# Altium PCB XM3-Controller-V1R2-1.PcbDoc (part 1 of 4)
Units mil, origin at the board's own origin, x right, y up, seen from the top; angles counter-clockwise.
Board outline 10629.92 x 4173.11 mil, 6 copper layers (TOP, GND1, LAYER3, PWR, GND2, BOTTOM), stack 62 mil thick; 362 components, 276 nets, 1145 pads, 503 vias.
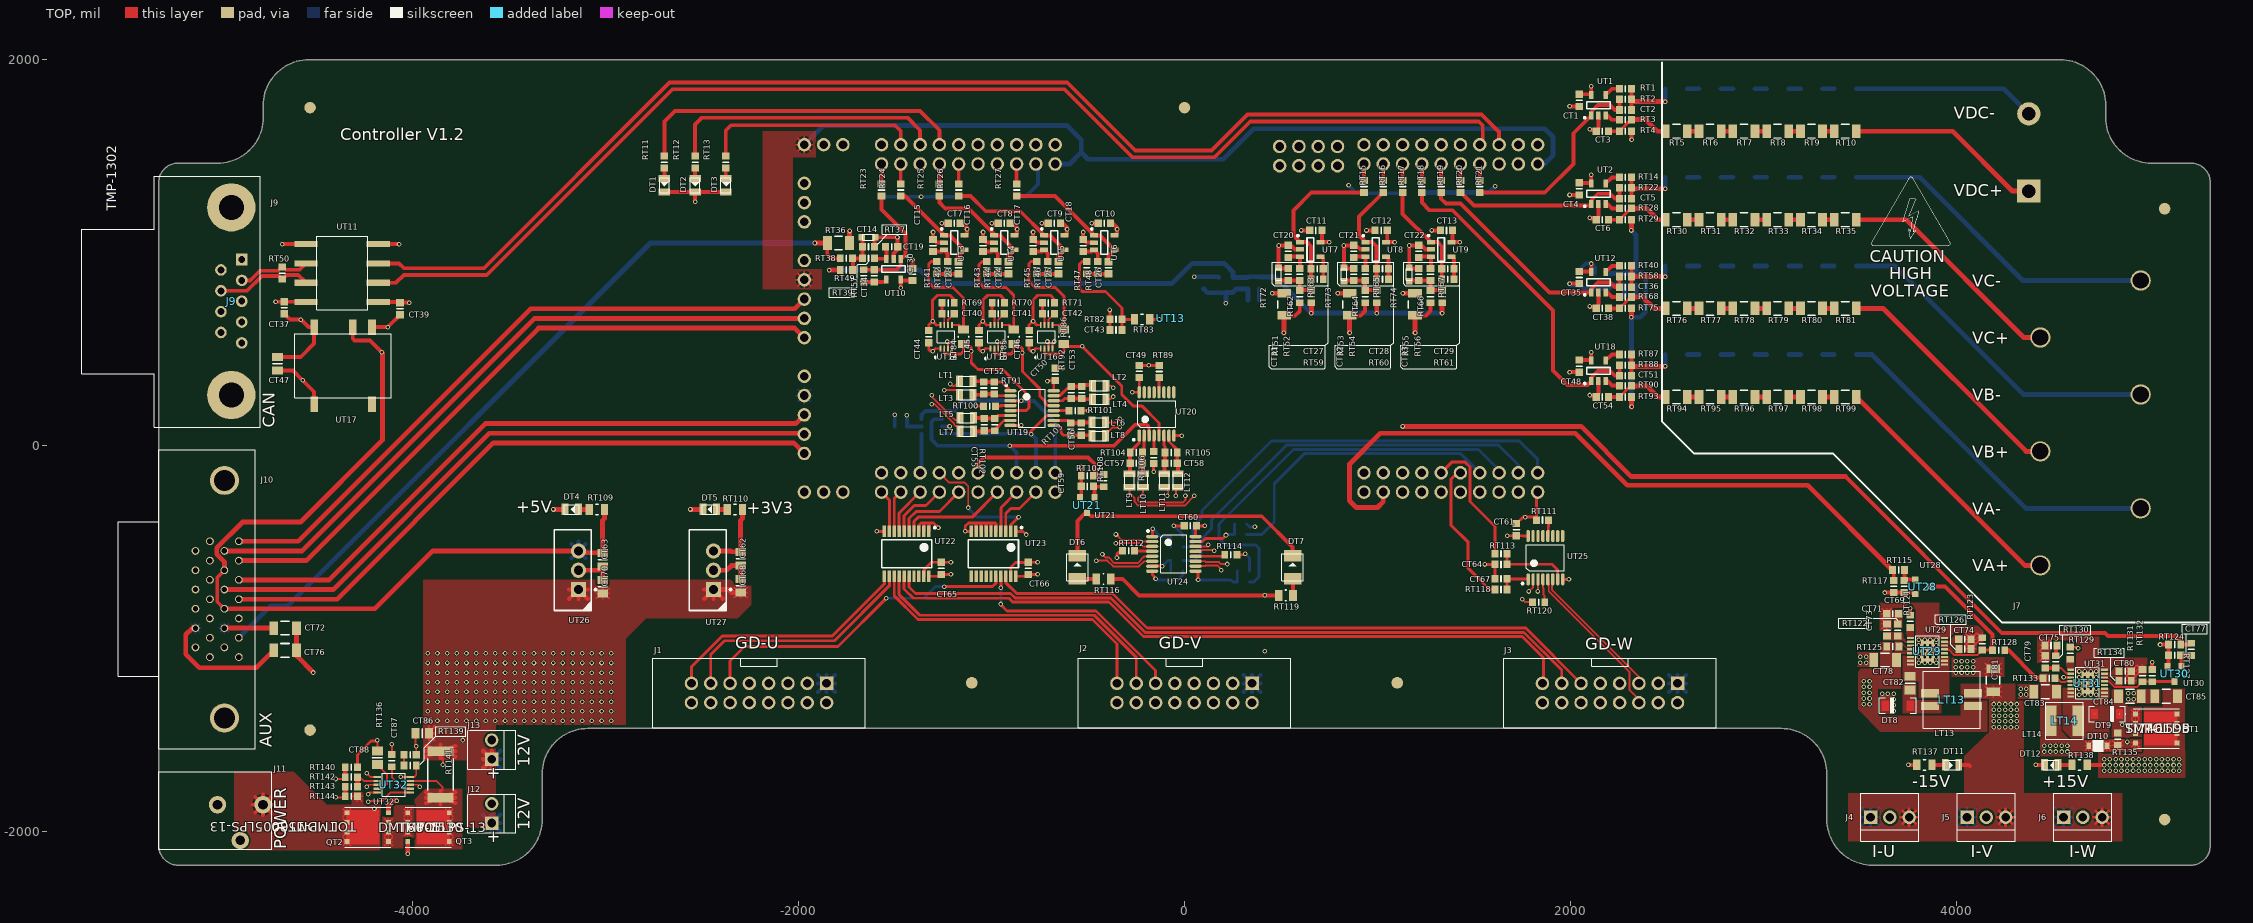
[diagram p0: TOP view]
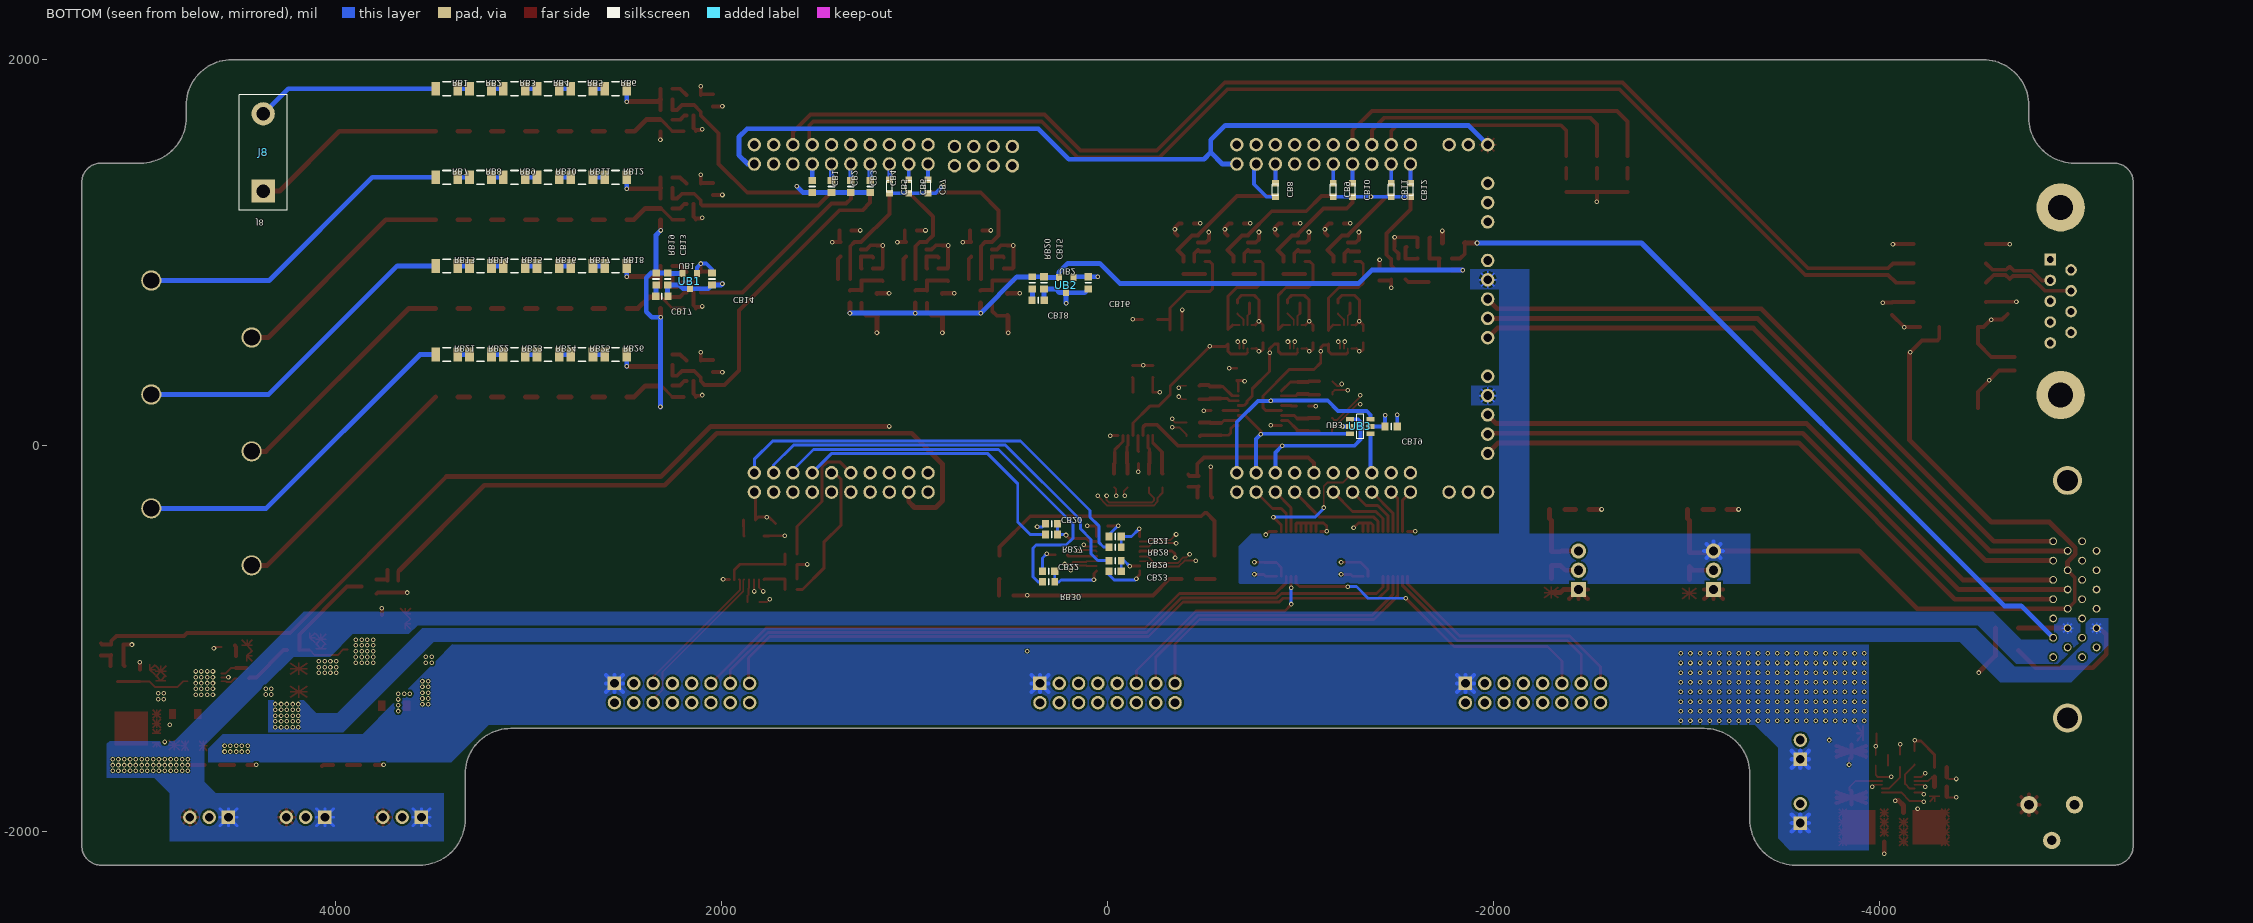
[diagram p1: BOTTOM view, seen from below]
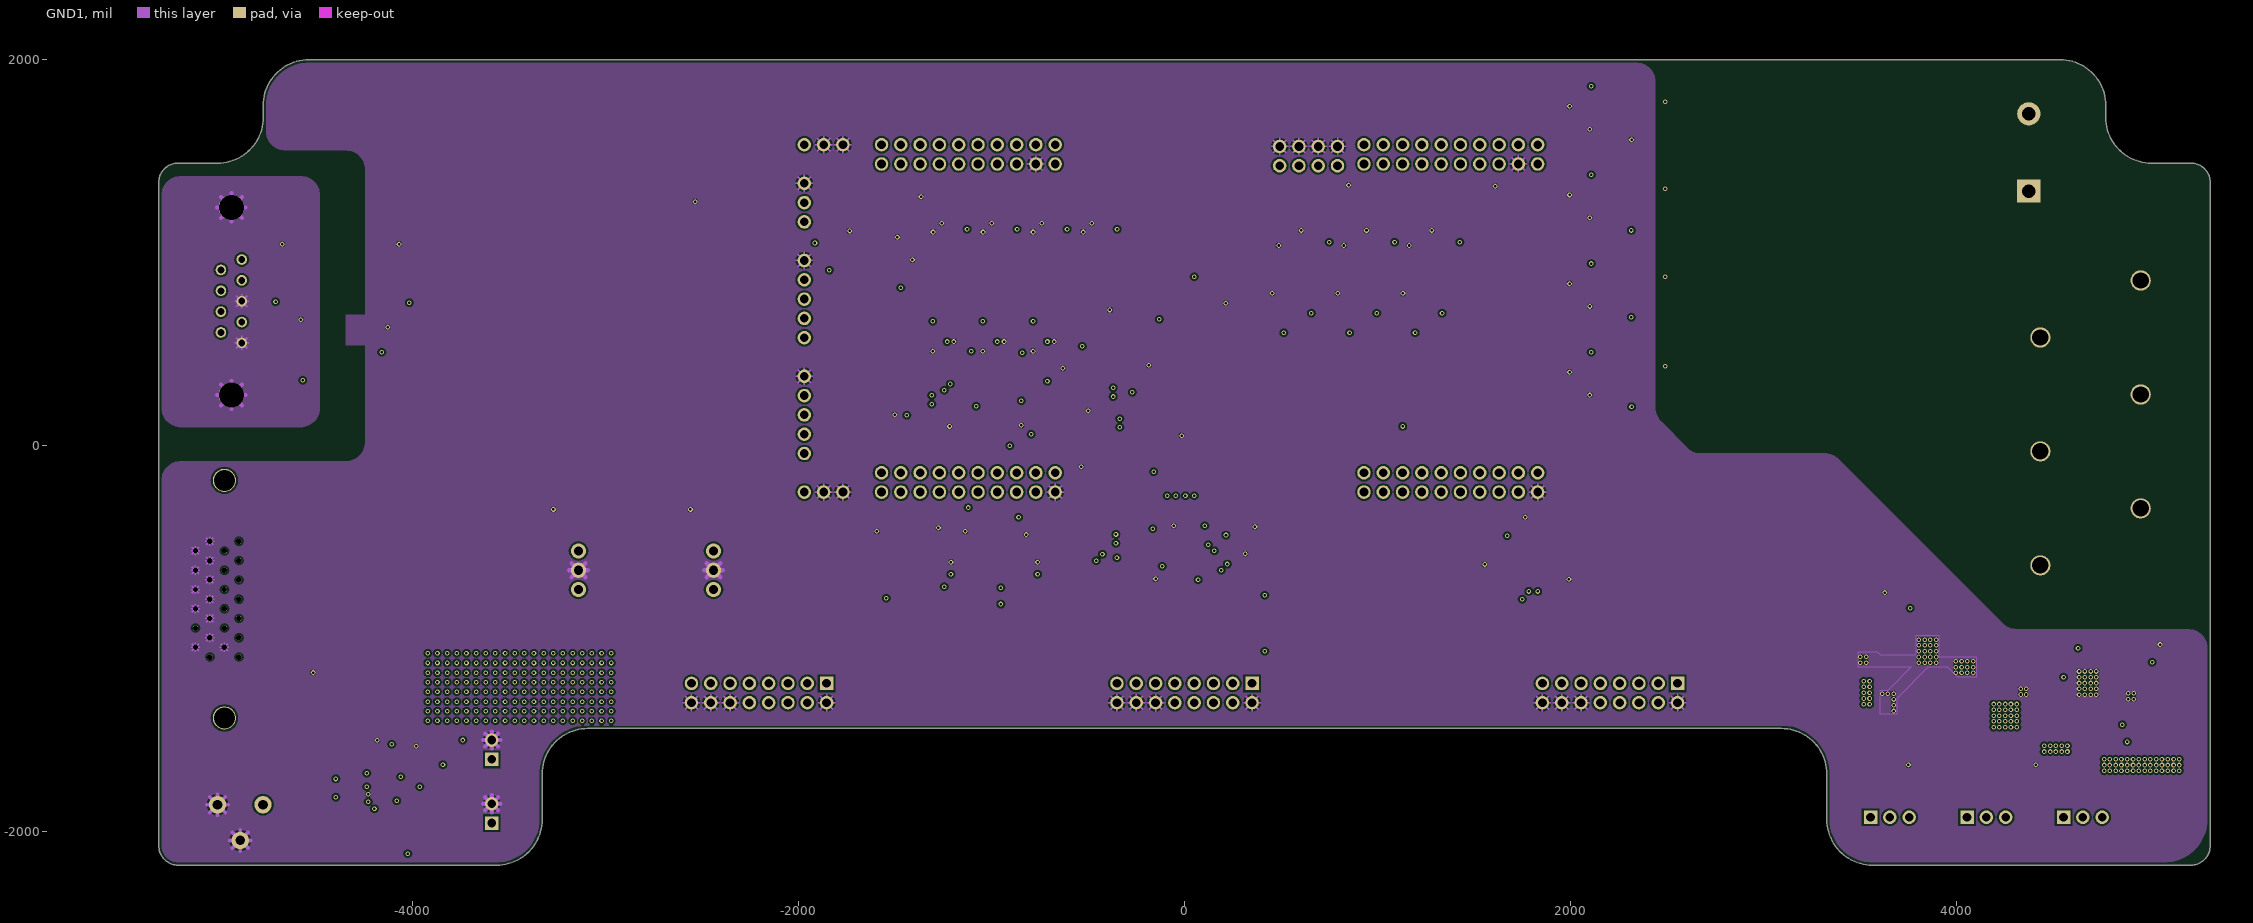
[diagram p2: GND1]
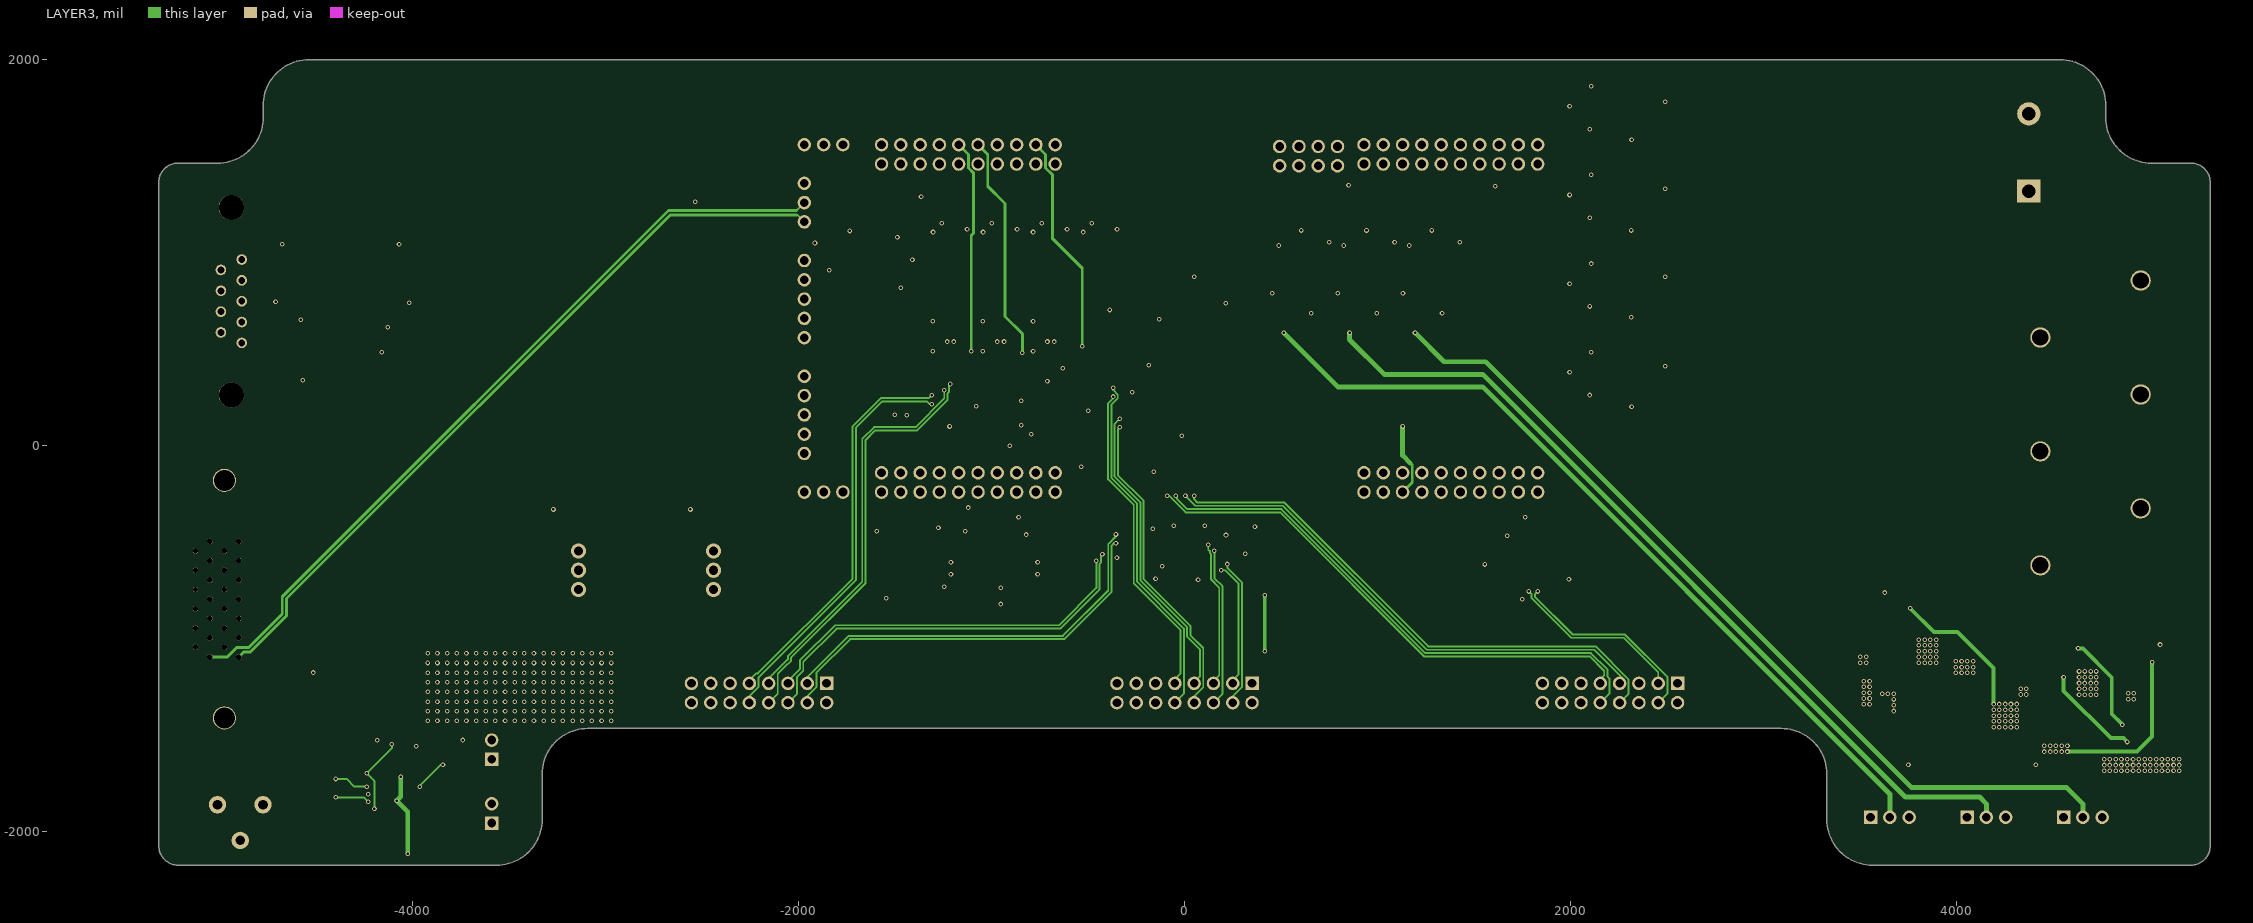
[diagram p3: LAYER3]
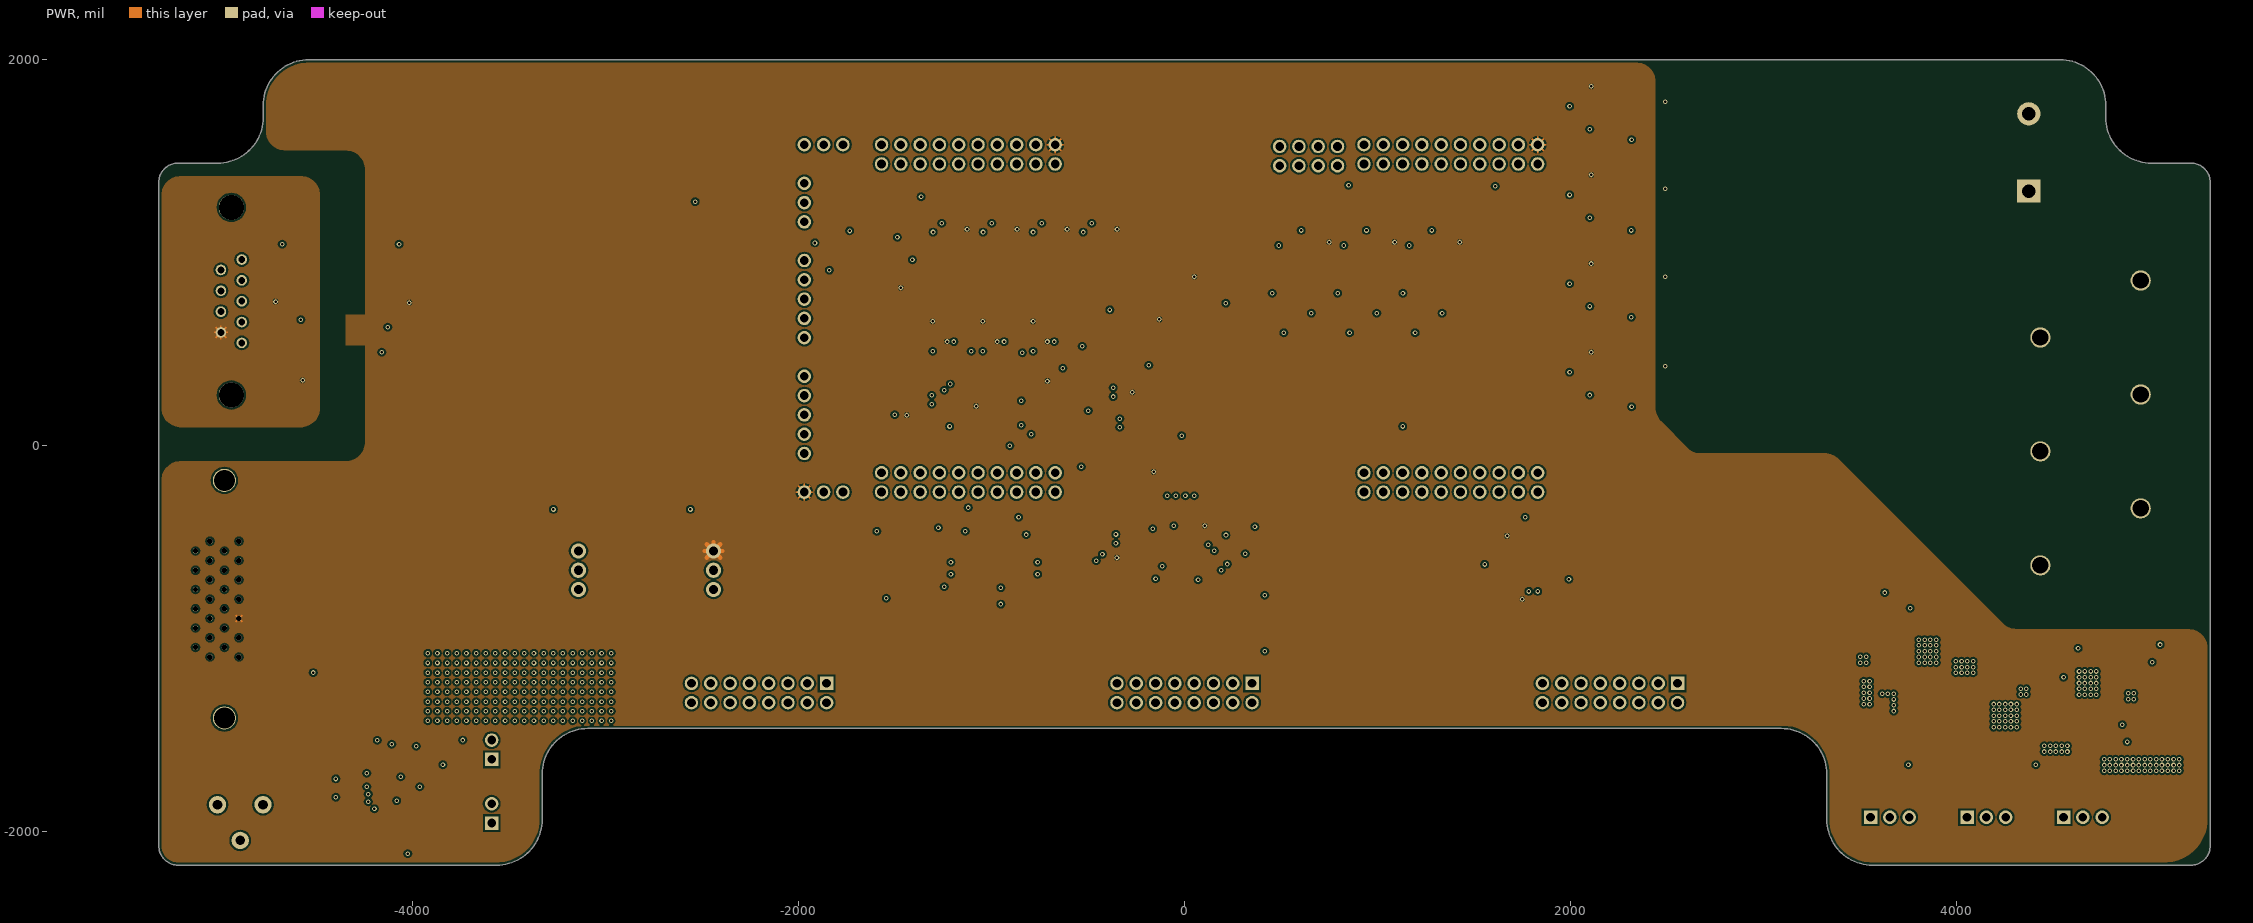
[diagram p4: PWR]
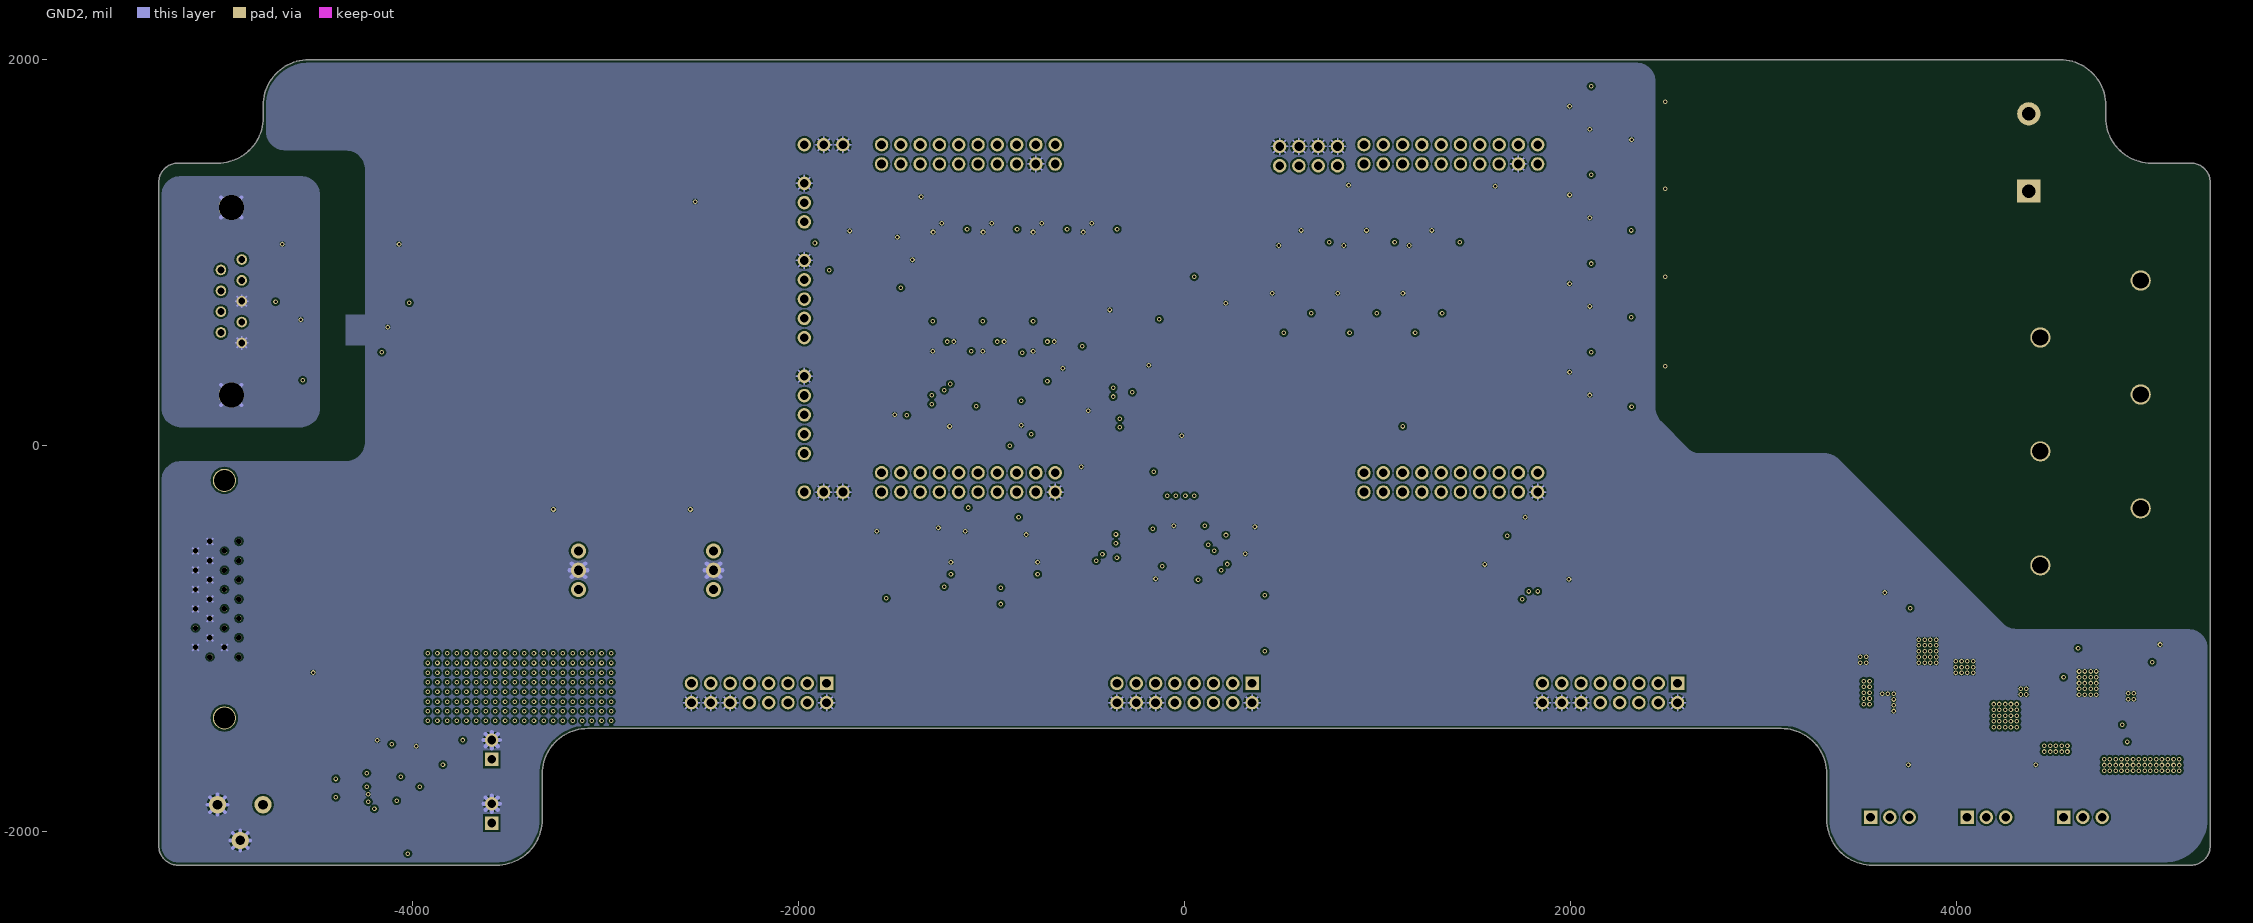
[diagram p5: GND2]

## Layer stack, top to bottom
Top Solder: solder mask 0.4, Solder Resist, Dk 3.5
TOP: signal copper 1.4
Dielectric 1: core 8, FR-4, Dk 4.5
GND1: signal copper 1.4
Dielectric2: core 8, FR-4, Dk 4.5
LAYER3: signal copper 1.4
Dielectric3: core 21.6, FR-4, Dk 4.5
PWR: signal copper 1.4
Dielectric4: core 8, FR-4, Dk 4.5
GND2: signal copper 1.4
Dielectric5: core 8, FR-4, Dk 4.5
BOTTOM: signal copper 1.4
Bottom Solder: solder mask 0.4, Solder Resist, Dk 3.5

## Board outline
-5009.84,1464.57 ccw(c-5009.84,1700.79) -4773.62,1700.79 -4773.62,1763.78 cw(c-4537.4,1763.78) -4537.4,2000 4537.4,2000 cw(c4537.4,1763.78) 4773.62,1763.78 4773.62,1700.79 ccw(c5009.84,1700.79) 5009.84,1464.57 5214.96,1464.57 cw(c5214.96,1364.57) 5314.96,1364.57 5314.96,-2073.11 cw(c5214.96,-2073.11) 5214.96,-2173.11 3564.68,-2173.11 cw(c3564.68,-1936.89) 3328.46,-1936.89 3328.46,-1700.79 ccw(c3092.24,-1700.79) 3092.24,-1464.57 -3092.24,-1464.57 ccw(c-3092.24,-1700.79) -3328.46,-1700.79 -3328.46,-1936.89 cw(c-3564.68,-1936.89) -3564.68,-2173.11 -5214.96,-2173.11 cw(c-5214.96,-2073.11) -5314.96,-2073.11 -5314.96,1364.57 cw(c-5214.96,1364.57) -5214.96,1464.57

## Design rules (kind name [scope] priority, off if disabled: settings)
Clearance [All] p1: gap=10 ignorepadtopadclearanceinfootprint=FALSE
DiffPairsRouting [All] p1: maxlimit=10 minlimit=10 mostfreqgap=10 toplayer_minwidth=15 toplayer_maxwidth=15 toplayer_prefwidth=15 midlayer1_minwidth=15 midlayer1_maxwidth=15 midlayer1_prefwidth=15 midlayer2_minwidth=15 midlayer2_maxwidth=15 midlayer2_prefwidth=15 midlayer3_minwidth=15 midlayer3_maxwidth=15 midlayer3_prefwidth=15 midlayer4_minwidth=15 midlayer4_maxwidth=15 midlayer4_prefwidth=15 bottomlayer_minwidth=15 bottomlayer_maxwidth=15 bottomlayer_prefwidth=15 maxuncoupledlength=500
PlaneConnect [All] p1: planeconnectstyle=Direct reliefexpansion=20 reliefentries=4 reliefconductorwidth=10 reliefairgap=10
PolygonConnect [All] p1: connectstyle=Direct reliefconductorwidth=10 reliefentries=4 polygonreliefangle="90 Angle" airgapwidth=10
RoutingVias [All] p1: holewidth=28 width=50 viastyle="Through Hole" minholewidth=28 minwidth=50 maxholewidth=28 maxwidth=50
SolderMaskExpansion [All] p1: expansion=4 istentingtop=FALSE
Width [All] p1: maxlimit=10 minlimit=10 preferedwidth=10 impedanceprofiledriven=TRUE minimp=24.700000 maximp=192.210000 favimp=19.760000
28 further rules are at their usual default settings.

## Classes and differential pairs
net class VBM: N45813 N45817 N45821 N51246 N51250 VB-M
differential pair C-RTD-: +C-RTD-N -C-RTD-P
differential pair CLS-PWM-: +CLS-PWM-N -CLS-PWM-P
differential pair CHS-PWM-: +CHS-PWM-N -CHS-PWM-P
differential pair C-FAULT-: +C-FAULT-N -C-FAULT-P
differential pair CANB: +CANBH -CANBL
differential pair CANA: +CANA-H -CANA-L
differential pair B-RTD-: +B-RTD-N -B-RTD-P
differential pair BLS-PWM-: +BLS-PWM-N -BLS-PWM-P
differential pair BHS-PWM-: +BHS-PWM-N -BHS-PWM-P
differential pair B-FAULT-: +B-FAULT-N -B-FAULT-P
differential pair A-RTD-: +A-RTD-N -A-RTD-P
differential pair ALS-PWM-: +ALS-PWM-N -ALS-PWM-P
differential pair AHS-PWM-: +AHS-PWM-N -AHS-PWM-P
differential pair A-FAULT-: +A-FAULT-N -A-FAULT-P

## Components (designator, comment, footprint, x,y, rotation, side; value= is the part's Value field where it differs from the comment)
CB1 "CAP_CAPC1608X90N_DISCRETE_0.27" CAPC1608X90N#1 1530,1343.5 r90 bottom
CB2 "CAP_CAPC1608X90N_DISCRETE_0.27" CAPC1608X90N#1 1430,1343.5 r90 bottom
CB3 "CAP_CAPC1608X90N_DISCRETE_0.27" CAPC1608X90N#1 1330,1343.5 r90 bottom
CB4 "CAP_CAPC1608X90N_DISCRETE_0.27" CAPC1608X90N#1 1230,1343.5 r90 bottom
CB5 "CAP_C_0603_DISCRETE_4700PF_TMP-" C_0603#1 1130,1343.5 r90 bottom
CB6 "CAP_C_0603_DISCRETE_4700PF_TMP-" C_0603#1 1030,1343.5 r90 bottom
CB7 "CAP_C_0603_DISCRETE_4700PF_TMP-" C_0603#1 930,1343.5 r90 bottom
CB8 "CAP_C_0603_DISCRETE_4700PF_TMP-" C_0603#1 -870,1325.22 r90 bottom
CB9 "CAP_C_0603_DISCRETE_4700PF_TMP-" C_0603#1 -1170,1325.22 r90 bottom
CB10 "CAP_C_0603_DISCRETE_4700PF_TMP-" C_0603#1 -1270,1325.22 r90 bottom
CB11 "CAP_C_0603_DISCRETE_4700PF_TMP-" C_0603#1 -1470,1325.22 r90 bottom
CB12 "CAP_C_0603_DISCRETE_4700PF_TMP-" C_0603#1 -1570,1325.22 r90 bottom
CB13 "CAP_CAPC1608X90N_DISCRETE_10000" CAPC1608X90N#1 2279.25,864.17 r90 bottom
CB14 "CAP_CAPC1608X87N_DISCRETE_0.1UF" CAPC1608X87N#1 2049.25,864.17 r90 bottom
CB15 "CAP_CAPC1608X90N_DISCRETE_10000" CAPC1608X90N#1 329.25,844.16 r90 bottom
CB16 "CAP_CAPC1608X87N_DISCRETE_0.1UF" CAPC1608X87N#1 99.25,844.16 r90 bottom
CB17 "CAP_CAPC1608X90N_DISCRETE_10UF_" CAPC1608X90N#2 2309.25,774.17 r180 bottom
CB18 "CAP_CAPC1608X90N_DISCRETE_10UF_" CAPC1608X90N#2 359.25,754.16 r180 bottom
CB19 "CAP_CAPC1608X87N_DISCRETE_0.1UF" CAPC1608X87N#2 -1470,100 r180 bottom
CB20 "CAP_CAPC1608X90N_DISCRETE_100PF" CAPC1608X90N#2 290,-405 r0 bottom
CB21 "CAP_CAPC1608X90N_DISCRETE_100PF" CAPC1608X90N#2 -40,-470 r0 bottom
CB22 "CAP_CAPC1608X90N_DISCRETE_100PF" CAPC1608X90N#2 305,-650 r0 bottom
CB23 "CAP_CAPC1608X90N_DISCRETE_100PF" CAPC1608X90N#2 -40,-650 r0 bottom
CT1 "CAP_CAPC1608X87N_DISCRETE_0.1UF" CAPC1608X87N#2 2045,1790 r270 top
CT2 "CAP_CAPC1608X90N_DISCRETE_4700P" CAPC1608X90N#2 2285,1740 r180 top
CT3 "CAP_CAPC1608X90N_DISCRETE_4700P" CAPC1608X90N#2 2165,1630 r0 top
CT4 "CAP_CAPC1608X87N_DISCRETE_0.1UF" CAPC1608X87N#2 2045,1330.94 r270 top
CT5 "CAP_CAPC1608X90N_DISCRETE_10000" CAPC1608X90N#2 2285,1280.94 r180 top
CT6 "CAP_CAPC1608X90N_DISCRETE_10000" CAPC1608X90N#2 2165,1170.94 r0 top
CT7 "CAP_CAPC1608X87N_DISCRETE_0.1UF" CAPC1608X87N#2 -1193.15,1152.4 r180 top
CT8 "CAP_CAPC1608X87N_DISCRETE_0.1UF" CAPC1608X87N#2 -933.97,1152.4 r180 top
CT9 "CAP_CAPC1608X87N_DISCRETE_0.1UF" CAPC1608X87N#2 -674.79,1152.4 r180 top
CT10 "CAP_CAPC1608X87N_DISCRETE_0.1UF" CAPC1608X87N#2 -415.61,1152.4 r180 top
CT11 "CAP_CAPC1608X87N_DISCRETE_0.1UF" CAPC1608X87N#2 680.44,1115.66 r180 top
CT12 "CAP_CAPC1608X87N_DISCRETE_0.1UF" CAPC1608X87N#2 1018.96,1115.66 r180 top
CT13 "CAP_CAPC1608X87N_DISCRETE_0.1UF" CAPC1608X87N#2 1357.48,1115.66 r180 top
CT14 "CAP_C_0603_DISCRETE_4700PF_TMP-" C_0603#2 -1637.5,1080.64 r0 top
CT15 "CAP_CAPC1608X90N_DISCRETE_10000" CAPC1608X90N#2 -1303.15,1037.4 r270 top
CT16 "CAP_CAPC1608X90N_DISCRETE_10000" CAPC1608X90N#2 -1043.97,1037.4 r270 top
CT17 "CAP_CAPC1608X90N_DISCRETE_10000" CAPC1608X90N#2 -784.79,1037.4 r270 top
CT18 "CAP_CAPC1608X90N_DISCRETE_4700P" CAPC1608X90N#2 -525.61,1037.4 r270 top
CT19 "CAP_CAPC1608X90N_DISCRETE_100PF" CAPC1608X90N#2 -1517.5,1030.64 r0 top
CT20 "CAP_CAPC1608X90N_DISCRETE_100PF" CAPC1608X90N#2 537.5,1007.69 r90 top
CT21 "CAP_CAPC1608X90N_DISCRETE_100PF" CAPC1608X90N#2 876.02,1007.69 r90 top
CT22 "CAP_CAPC1608X90N_DISCRETE_100PF" CAPC1608X90N#2 1214.54,1007.69 r90 top
CT23 "CAP_CAPC1608X90N_DISCRETE_10000" CAPC1608X90N#2 -1171.27,922.4 r90 top
CT24 "CAP_CAPC1608X90N_DISCRETE_10000" CAPC1608X90N#2 -912.09,922.4 r90 top
CT25 "CAP_CAPC1608X90N_DISCRETE_10000" CAPC1608X90N#2 -652.91,922.4 r90 top
CT26 "CAP_CAPC1608X90N_DISCRETE_10000" CAPC1608X90N#2 -393.73,922.4 r90 top
CT27 "CAP_CAPC1608X90N_DISCRETE_100PF" CAPC1608X90N#2 687.5,917.69 r180 top
CT28 "CAP_CAPC1608X90N_DISCRETE_100PF" CAPC1608X90N#2 1026.02,917.69 r180 top
CT29 "CAP_CAPC1608X90N_DISCRETE_100PF" CAPC1608X90N#2 1364.54,917.69 r180 top
CT30 "CAP_CAPC1608X87N_DISCRETE_0.1UF" CAPC1608X87N#2 -1409.53,887.7 r90 top
CT31 "CAP_C_0603_DISCRETE_4700PF_TMP-" C_0603#2 487.5,887.69 r90 top
CT32 "CAP_C_0603_DISCRETE_4700PF_TMP-" C_0603#2 826.02,887.69 r90 top
CT33 "CAP_C_0603_DISCRETE_4700PF_TMP-" C_0603#2 1164.54,887.69 r90 top
CT34 "CAP_CAPC1608X90N_DISCRETE_100PF" CAPC1608X90N#2 -1607.5,880.64 r90 top
CT35 "CAP_CAPC1608X87N_DISCRETE_0.1UF" CAPC1608X87N#2 2045,871.88 r270 top
CT36 "CAP_CAPC1608X90N_DISCRETE_10000" CAPC1608X90N#2 2285,821.88 r180 top
CT37 "CAP_CAPC1608X87N_DISCRETE_0.1UF" CAPC1608X87N#2 -4665,715 r270 top
CT38 "CAP_CAPC1608X90N_DISCRETE_10000" CAPC1608X90N#2 2165,711.88 r0 top
CT39 "CAP_CAPC1608X87N_DISCRETE_0.1UF" CAPC1608X87N#2 -4065,710 r270 top
CT40 "CAP_CAPC1608X90N_DISCRETE_10000" CAPC1608X90N#2 -1225,685 r0 top
CT41 "CAP_CAPC1608X90N_DISCRETE_10000" CAPC1608X90N#2 -965,685 r0 top
CT42 "CAP_CAPC1608X90N_DISCRETE_10000" CAPC1608X90N#2 -705,685 r0 top
CT43 "CAP_CAPC1608X90N_DISCRETE_100PF" CAPC1608X90N#2 -355,600 r0 top
CT44 "CAP_CAPC1608X87N_DISCRETE_0.1UF" CAPC1608X87N#2 -1325,565 r270 top
CT45 "CAP_CAPC1608X87N_DISCRETE_0.1UF" CAPC1608X87N#2 -1065,565 r270 top
CT46 "CAP_CAPC1608X87N_DISCRETE_0.1UF" CAPC1608X87N#2 -805,565 r270 top
CT47 "CAP_CAPC2012X135N_DISCRETE_10UF" CAPC2012X135N -4700,425 r90 top
CT48 "CAP_CAPC1608X87N_DISCRETE_0.1UF" CAPC1608X87N#2 2045,412.82 r270 top
CT49 "CAP_CAPC1608X87N_DISCRETE_0.1UF" CAPC1608X87N#2 -235,385 r90 top
CT50 "CAP_CAPC1608X87N_DISCRETE_0.1UF" CAPC1608X87N#2 -670,370 r90 top
CT51 "CAP_CAPC1608X90N_DISCRETE_10000" CAPC1608X90N#2 2285,362.82 r180 top
CT52 "CAP_CAPC1608X90N_DISCRETE_27PF_" CAPC1608X90N#2 -1040.5,299.17 r90 top
CT53 "CAP_CAPC1608X90N_DISCRETE_27PF_" CAPC1608X90N#2 -531.5,275.84 r90 top
CT54 "CAP_CAPC1608X90N_DISCRETE_10000" CAPC1608X90N#2 2165,252.82 r0 top
CT55 "CAP_CAPC1608X90N_DISCRETE_27PF_" CAPC1608X90N#2 -1038.5,109.17 r270 top
CT56 "CAP_CAPC1608X90N_DISCRETE_27PF_" CAPC1608X90N#2 -534.5,85.84 r270 top
CT57 "CAP_CAPC1608X90N_DISCRETE_27PF_" CAPC1608X90N#2 -250,-90 r180 top
CT58 "CAP_CAPC1608X90N_DISCRETE_27PF_" CAPC1608X90N#2 -69.16,-90 r0 top
CT59 "CAP_CAPC1608X90N_DISCRETE_100PF" CAPC1608X90N#2 -503.29,-210.85 r180 top
CT60 "CAP_CAPC1608X87N_DISCRETE_0.1UF" CAPC1608X87N#2 30,-415 r180 top
CT61 "CAP_CAPC1608X87N_DISCRETE_0.1UF" CAPC1608X87N#2 1720,-435 r90 top
CT62 "CAP_CAPC2012X135N_DISCRETE_10UF" CAPC2012X135N -2300,-585 r270 top
CT63 "CAP_CAPC2012X135N_DISCRETE_10UF" CAPC2012X135N -3015,-590 r270 top
CT64 "CAP_CAPC1608X90N_DISCRETE_100PF" CAPC1608X90N#2 1640,-615 r180 top
CT65 "CAP_CAPC1608X87N_DISCRETE_0.1UF" CAPC1608X87N#2 -1260,-635 r90 top
CT66 "CAP_CAPC1608X87N_DISCRETE_0.1UF" CAPC1608X87N#2 -810,-635 r90 top
CT67 "CAP_CAPC1608X90N_DISCRETE_100PF" CAPC1608X90N#2 1640,-690 r180 top
CT68 "CAP_CAPC2012X135N_DISCRETE_10UF" CAPC2012X135N -2300,-725 r90 top
CT69 "CAP_CAPC1608X90N_DISCRETE_100PF" CAPC1608X90N#2 3730,-729 r270 top
CT70 "CAP_CAPC2012X135N_DISCRETE_10UF" CAPC2012X135N -3015,-730 r90 top
CT71 "CAP_CAPC1608X90N_DISCRETE_1000P" CAPC1608X90N#2 3670,-870 r180 top
CT72 "CAP_CAPC3216X180N_DISCRETE_10 U" CAPC3216X180N -4660,-945 r0 top
CT73 "CAP_CAPC1608X90N_DISCRETE_56 PF" CAPC1608X90N#2 3640,-955 r270 top
CT74 "CAP_CAPC1608X90N_DISCRETE_0.1UF" CAPC1608X90N#2 4044,-1003 r180 top
CT75 "CAP_CAPC1608X90N_DISCRETE_1000P" CAPC1608X90N#2 4490,-1035 r180 top
CT76 "CAP_CAPC3216X180N_DISCRETE_10 U" CAPC3216X180N -4660,-1060 r0 top
CT77 "CAP_CAPC1608X90N_DISCRETE_100PF" CAPC1608X90N#2 5131,-1085.01 r180 top
CT78 "CAP_CAPC3216X180N_DISCRETE_4.7U" CAPC3216X180N 3630,-1110 r180 top
CT79 "CAP_CAPC1608X90N_DISCRETE_56 PF" CAPC1608X90N#2 4460,-1120 r270 top
CT80 "CAP_CAPC1608X90N_DISCRETE_0.1UF" CAPC1608X90N#2 4874,-1168 r180 top
CT81 "CAP_CAPC3216X180N_DISCRETE_10 U" CAPC3216X180N 4190,-1215 r90 top
CT82 "CAP_CAPC2012X70N_DISCRETE_1UF_T" CAPC2012X70N 3760,-1230 r270 top
CT83 "CAP_CAPC3216X180N_DISCRETE_4.7U" CAPC3216X180N 4460,-1275 r180 top
CT84 "CAP_CAPC3216X180N_DISCRETE_4.7U" CAPC3216X180N 4899,-1298 r0 top
CT85 "CAP_CAPC3216X180N_DISCRETE_10 U" CAPC3216X180N 5087,-1298 r180 top
CT86 "CAP_CAPC2012X135N_DISCRETE_10UF" CAPC2012X135N -3950,-1490 r180 top
CT87 "CAP_CAPC1608X90N_DISCRETE_4700P" CAPC1608X90N#2 -4012.5,-1601.67 r0 top
CT88 "CAP_CAPC2012X70N_DISCRETE_0.022" CAPC2012X70N -4182.5,-1616.67 r90 top
DT1 "LED_0_D_0805_DISCRETE_LH R974-L" D_0805 -2695,1350 r270 top
DT2 "LED_0_D_0805_DISCRETE_LTST-C1_1" D_0805 -2535.94,1350 r270 top
DT3 "LED_0_D_0805_DISCRETE_LG R971-K" D_0805 -2376.88,1350 r270 top
DT4 "LED_0_D_0805_DISCRETE_LTST-C171" D_0805 -3175,-330 r180 top
DT5 "LED_0_D_0805_DISCRETE_LTST-C171" D_0805 -2460,-330 r180 top
DT6 "LED - PURPLE_D_1409_DISCRETE_AA" D_1409 -555,-630 r90 top
DT7 "LED - PURPLE_D_1409_DISCRETE_AA" D_1409 560,-630 r90 top
DT8 "DIODE_SCHOTTKY_0_SOD-123F-AC_DI" SOD-123F-AC 3696,-1347 r180 top
DT9 "DIODE_SCHOTTKY_0_SOD-123F-AC_DI" SOD-123F-AC 4780,-1390 r0 top
DT10 "DIODE_SCHOTTKY_C2_A1_0_SOD-323-" SOD-323-AC 4730,-1555 r0 top
DT11 "LED_0_D_0805_DISCRETE_LTST-C171" D_0805 3977,-1653.47 r0 top
DT12 "LED_0_D_0805_DISCRETE_LTST-C171" D_0805 4491,-1653.47 r180 top
J1 "CON16A_CORRECTED_CON_2X8_SHROUD" CON_2X8_SHROUDED_CORRECTED -2204.72,-1281.36 r270 top
J2 "CON16A_CORRECTED_CON_2X8_SHROUD" CON_2X8_SHROUDED_CORRECTED 0,-1281.36 r270 top
J3 "CON16A_CORRECTED_CON_2X8_SHROUD" CON_2X8_SHROUDED_CORRECTED 2204.72,-1281.36 r270 top
J4 "CON3_CON_1X3_VERT_LOCK_IO_00222" CON_1X3_VERT_LOCK 3655,-1925 r90 top
J5 "CON3_CON_1X3_VERT_LOCK_IO_00222" CON_1X3_VERT_LOCK 4155,-1925 r90 top
J6 "CON3_CON_1X3_VERT_LOCK_IO_00222" CON_1X3_VERT_LOCK 4655,-1925 r90 top
J7 "HDR_1X6_M_PHOENIX_SPT5_6PIN_IO_" PHOENIX_SPT5_6PIN 4835.59,41.42 r90 top
J8 "CON2_2POS_400MIL_TERMINAL_CON2" 2POS_400MIL_TERMINAL 4375,1520 r270 bottom
J9 "DSUB - NI CAN INTERFACE_0_DB9_I" DB9 -5263,749 r90 top
J10 "CONN CENT RCPT 26_MDR-26_IO_102" MDR-26 -5170,-795 r270 top
J11 "POWER_JACK_POWERJACK-PJ102AH_IO" POWERJACK-PJ102AH -5022.5,-1890 r270 top
J12 "1X2 100MIL_CON_1X2_VERT_LOCK_IO" CON_1X2_VERT_LOCK -3590,-1905 r180 top
J13 "1X2 100MIL_CON_1X2_VERT_LOCK_IO" CON_1X2_VERT_LOCK -3590,-1575 r180 top
LT1 "INDUCTOR_L_0805_DISCRETE_1UH_TM" L_0805 -1130.5,334.17 r0 top
LT2 "INDUCTOR_L_0805_DISCRETE_1UH_TM" L_0805 -441.5,310.84 r180 top
LT3 "INDUCTOR_L_0805_DISCRETE_1UH_TM" L_0805 -1130.5,264.17 r0 top
LT4 "INDUCTOR_L_0805_DISCRETE_1UH_TM" L_0805 -441.5,240.84 r180 top
LT5 "INDUCTOR_L_0805_DISCRETE_1UH_TM" L_0805 -1128.5,144.17 r0 top
LT6 "INDUCTOR_L_0805_DISCRETE_1UH_TM" L_0805 -444.5,120.84 r180 top
LT7 "INDUCTOR_L_0805_DISCRETE_1UH_TM" L_0805 -1128.5,74.17 r0 top
LT8 "INDUCTOR_L_0805_DISCRETE_1UH_TM" L_0805 -444.5,50.84 r180 top
LT9 "INDUCTOR_L_0805_DISCRETE_1UH_TM" L_0805 -285,-180 r90 top
LT10 "INDUCTOR_L_0805_DISCRETE_1UH_TM" L_0805 -215,-180 r90 top
LT11 "INDUCTOR_L_0805_DISCRETE_1UH_TM" L_0805 -104.16,-180 r90 top
LT12 "INDUCTOR_L_0805_DISCRETE_1UH_TM" L_0805 -34.16,-180 r90 top
LT13 "COUPLED_INDUCTOR_IND-MSD7342_6." IND-MSD7342 3975,-1315 r180 top
LT14 "IND_IND-5040_DISCRETE_3.3UH_TMP" IND-5040 4560,-1425 r0 top
QT1 "MOSFET_P_PSO8_POWER-SO8_DISCRET" POWER-SO8 5035,-1465 r0 top
QT2 "MOSFET_N_PSO8_POWER-SO8_DISCRET" POWER-SO8 -4232.5,-1976.67 r180 top
QT3 "MOSFET_N_PSO8_POWER-SO8_DISCRET" POWER-SO8 -3917.5,-1976.67 r0 top
RB1 "RES_RESC3216X65N_DISCRETE_249 K" RESC3216X65N 3423.59,1850 r180 bottom
RB2 "RES_RESC3216X65N_DISCRETE_249 K" RESC3216X65N 3248.59,1850 r180 bottom
RB3 "RES_RESC3216X65N_DISCRETE_249 K" RESC3216X65N 3073.59,1850 r180 bottom
RB4 "RES_RESC3216X65N_DISCRETE_249 K" RESC3216X65N 2898.59,1850 r180 bottom
RB5 "RES_RESC3216X65N_DISCRETE_249 K" RESC3216X65N 2723.59,1850 r180 bottom
RB6 "RES_RESC3216X65N_DISCRETE_249 K" RESC3216X65N 2548.59,1850 r180 bottom
RB7 "RES_RESC3216X65N_DISCRETE_249 K" RESC3216X65N 3423.59,1390.94 r180 bottom
RB8 "RES_RESC3216X65N_DISCRETE_249 K" RESC3216X65N 3248.59,1390.94 r180 bottom
RB9 "RES_RESC3216X65N_DISCRETE_249 K" RESC3216X65N 3073.58,1390.94 r180 bottom
RB10 "RES_RESC3216X65N_DISCRETE_249 K" RESC3216X65N 2898.59,1390.94 r180 bottom
RB11 "RES_RESC3216X65N_DISCRETE_249 K" RESC3216X65N 2723.59,1390.94 r180 bottom
RB12 "RES_RESC3216X65N_DISCRETE_249 K" RESC3216X65N 2548.59,1390.94 r180 bottom
RB13 "RES_RESC3216X65N_DISCRETE_249 K" RESC3216X65N 3423.59,931.88 r180 bottom
RB14 "RES_RESC3216X65N_DISCRETE_249 K" RESC3216X65N 3248.59,931.88 r180 bottom
RB15 "RES_RESC3216X65N_DISCRETE_249 K" RESC3216X65N 3073.58,931.88 r180 bottom
RB16 "RES_RESC3216X65N_DISCRETE_249 K" RESC3216X65N 2898.59,931.88 r180 bottom
RB17 "RES_RESC3216X65N_DISCRETE_249 K" RESC3216X65N 2723.59,931.88 r180 bottom
RB18 "RES_RESC3216X65N_DISCRETE_249 K" RESC3216X65N 2548.59,931.88 r180 bottom
RB19 "RES_RESC1608X55N_DISCRETE_2K_TM" RESC1608X55N#1 2339.25,864.17 r90 bottom
RB20 "RES_RESC1608X55N_DISCRETE_2K_TM" RESC1608X55N#1 389.25,844.16 r90 bottom
RB21 "RES_RESC3216X65N_DISCRETE_249 K" RESC3216X65N 3423.59,472.82 r180 bottom
RB22 "RES_RESC3216X65N_DISCRETE_249 K" RESC3216X65N 3248.59,472.82 r180 bottom
RB23 "RES_RESC3216X65N_DISCRETE_249 K" RESC3216X65N 3073.58,472.82 r180 bottom
RB24 "RES_RESC3216X65N_DISCRETE_249 K" RESC3216X65N 2898.59,472.82 r180 bottom
RB25 "RES_RESC3216X65N_DISCRETE_249 K" RESC3216X65N 2723.59,472.82 r180 bottom
RB26 "RES_RESC3216X65N_DISCRETE_249 K" RESC3216X65N 2548.59,472.82 r180 bottom
RB27 "R_RESC1608X55N_DISCRETE_120_TMP" RESC1608X55N#2 290,-460 r180 bottom
RB28 "R_RESC1608X55N_DISCRETE_120_TMP" RESC1608X55N#2 -40,-525 r180 bottom
RB29 "R_RESC1608X55N_DISCRETE_120_TMP" RESC1608X55N#2 -40,-595 r180 bottom
RB30 "R_RESC1608X55N_DISCRETE_120_TMP" RESC1608X55N#2 305,-705 r180 bottom
RT1 "RES_RESC1608X55N_DISCRETE_4.99K" RESC1608X55N#2 2285,1850 r180 top
RT2 "RES_RESC1608X55N_DISCRETE_3.74" RESC1608X55N#2 2285,1795 r180 top
RT3 "RES_RESC1608X55N_DISCRETE_4.99K" RESC1608X55N#2 2285,1688.94 r180 top
RT4 "RES_RESC1608X55N_DISCRETE_3.74" RESC1608X55N#2 2285,1630 r180 top
RT5 "RES_RESC3216X65N_DISCRETE_249 K" RESC3216X65N 2548.59,1630 r180 top
RT6 "RES_RESC3216X65N_DISCRETE_249 K" RESC3216X65N 2723.59,1630 r180 top
RT7 "RES_RESC3216X65N_DISCRETE_249 K" RESC3216X65N 2898.59,1630 r180 top
RT8 "RES_RESC3216X65N_DISCRETE_249 K" RESC3216X65N 3073.59,1630 r180 top
RT9 "RES_RESC3216X65N_DISCRETE_249 K" RESC3216X65N 3248.59,1630 r180 top
RT10 "RES_RESC3216X65N_DISCRETE_249 K" RESC3216X65N 3423.59,1630 r180 top
RT11 "RES_RESC1608X55N_DISCRETE_680_T" RESC1608X55N#2 -2695,1470 r270 top
RT12 "RES_RESC1608X55N_DISCRETE_680_T" RESC1608X55N#2 -2535.94,1470 r270 top
RT13 "RES_RESC1608X55N_DISCRETE_680_T" RESC1608X55N#2 -2376.88,1470 r270 top
RT14 "RES_RESC1608X55N_DISCRETE_4.99K" RESC1608X55N#2 2285,1390.94 r180 top
RT15 "RES_RESC1608X55N_DISCRETE_49.9_" RESC1608X55N#2 930,1343.5 r90 top
RT16 "RES_RESC1608X55N_DISCRETE_49.9_" RESC1608X55N#2 1030,1343.5 r90 top
RT17 "RES_RESC1608X55N_DISCRETE_49.9_" RESC1608X55N#2 1130,1343.5 r90 top
RT18 "RES_RESC1608X55N_DISCRETE_49.9_" RESC1608X55N#2 1230,1343.5 r90 top
RT19 "RES_RESC1608X55N_DISCRETE_49.9_" RESC1608X55N#2 1330,1343.5 r90 top
RT20 "RES_RESC1608X55N_DISCRETE_49.9_" RESC1608X55N#2 1430,1343.5 r90 top
RT21 "RES_RESC1608X55N_DISCRETE_49.9_" RESC1608X55N#2 1530,1343.5 r90 top
RT22 "RES_RESC1608X55N_DISCRETE_1.8 K" RESC1608X55N#2 2285,1335.94 r180 top
RT23 "RES_RESC1608X55N_DISCRETE_49.9_" RESC1608X55N#2 -1570,1325.22 r90 top
RT24 "RES_RESC1608X55N_DISCRETE_49.9_" RESC1608X55N#2 -1470,1325.22 r90 top
RT25 "RES_RESC1608X55N_DISCRETE_49.9_" RESC1608X55N#2 -1270,1325.22 r90 top
RT26 "RES_RESC1608X55N_DISCRETE_49.9_" RESC1608X55N#2 -1170,1325.22 r90 top
RT27 "RES_RESC1608X55N_DISCRETE_49.9_" RESC1608X55N#2 -870,1325.22 r90 top
RT28 "RES_RESC1608X55N_DISCRETE_4.99K" RESC1608X55N#2 2285,1229.88 r180 top
RT29 "RES_RESC1608X55N_DISCRETE_1.8 K" RESC1608X55N#2 2285,1170.94 r180 top
RT30 "RES_RESC3216X65N_DISCRETE_249 K" RESC3216X65N 2548.6,1170.94 r180 top
RT31 "RES_RESC3216X65N_DISCRETE_249 K" RESC3216X65N 2723.6,1170.95 r180 top
RT32 "RES_RESC3216X65N_DISCRETE_249 K" RESC3216X65N 2898.58,1170.94 r180 top
RT33 "RES_RESC3216X65N_DISCRETE_249 K" RESC3216X65N 3073.6,1170.94 r180 top
RT34 "RES_RESC3216X65N_DISCRETE_249 K" RESC3216X65N 3248.6,1170.94 r180 top
RT35 "RES_RESC3216X65N_DISCRETE_249 K" RESC3216X65N 3423.58,1170.94 r180 top
RT36 "RES_RESC3216X65N_DISCRETE_27_TM" RESC3216X65N -1792.5,1050.64 r0 top
RT37 "R_RESC1608X55N_DISCRETE_4.02 KO" RESC1608X55N#2 -1637.5,1030.64 r180 top
RT38 "RES_RESC1608X55N_DISCRETE_2K_TM" RESC1608X55N#2 -1752.5,970.64 r0 top
RT39 "R_RESC1608X55N_DISCRETE_7.15 KO" RESC1608X55N#2 -1637.5,970.64 r0 top
RT40 "RES_RESC1608X55N_DISCRETE_4.99K" RESC1608X55N#2 2285,931.88 r180 top
RT41 "RES_RESC1608X55N_DISCRETE_30.1K" RESC1608X55N#2 -1283.15,922.4 r270 top
RT42 "RES_RESC1608X55N_DISCRETE_30.1K" RESC1608X55N#2 -1227.21,922.4 r90 top
RT43 "RES_RESC1608X55N_DISCRETE_30.1K" RESC1608X55N#2 -1023.97,922.4 r270 top
RT44 "RES_RESC1608X55N_DISCRETE_30.1K" RESC1608X55N#2 -968.03,922.4 r90 top
RT45 "RES_RESC1608X55N_DISCRETE_30.1K" RESC1608X55N#2 -764.79,922.4 r270 top
RT46 "RES_RESC1608X55N_DISCRETE_30.1K" RESC1608X55N#2 -708.85,922.4 r90 top
RT47 "RES_RESC1608X55N_DISCRETE_30.1K" RESC1608X55N#2 -505.61,922.4 r270 top
RT48 "RES_RESC1608X55N_DISCRETE_17.8K" RESC1608X55N#2 -449.67,922.4 r90 top
RT49 "R_RESC1608X55N_DISCRETE_1.33 K_" RESC1608X55N#2 -1752.5,910.64 r0 top
RT50 "R_RESC1608X55N_DISCRETE_120_TMP" RESC1608X55N#2 -4675,895 r90 top
RT51 "R_RESC1608X55N_DISCRETE_4.02 KO" RESC1608X55N#2 537.5,887.69 r270 top
RT52 "R_RESC1608X55N_DISCRETE_7.15 KO" RESC1608X55N#2 597.5,887.69 r90 top
RT53 "R_RESC1608X55N_DISCRETE_4.02 KO" RESC1608X55N#2 876.02,887.69 r270 top
RT54 "R_RESC1608X55N_DISCRETE_7.15 KO" RESC1608X55N#2 936.02,887.69 r90 top
RT55 "R_RESC1608X55N_DISCRETE_4.02 KO" RESC1608X55N#2 1214.54,887.69 r270 top
RT56 "R_RESC1608X55N_DISCRETE_7.15 KO" RESC1608X55N#2 1274.54,887.69 r90 top
RT57 "R_RESC1608X55N_DISCRETE_7.87 KO" RESC1608X55N#2 -1662.5,880.64 r90 top
RT58 "RES_RESC1608X55N_DISCRETE_1.8 K" RESC1608X55N#2 2285,876.88 r180 top
RT59 "R_RESC1608X55N_DISCRETE_7.87 KO" RESC1608X55N#2 687.5,862.69 r180 top
RT60 "R_RESC1608X55N_DISCRETE_7.87 KO" RESC1608X55N#2 1026.02,862.69 r180 top
RT61 "R_RESC1608X55N_DISCRETE_7.87 KO" RESC1608X55N#2 1364.54,862.69 r180 top
RT62 "RES_RESC1608X55N_DISCRETE_2K_TM" RESC1608X55N#2 597.5,772.69 r90 top
RT63 "R_RESC1608X55N_DISCRETE_1.33 K_" RESC1608X55N#2 657.5,772.69 r90 top
RT64 "RES_RESC1608X55N_DISCRETE_2K_TM" RESC1608X55N#2 936.02,772.69 r90 top
RT65 "R_RESC1608X55N_DISCRETE_1.33 K_" RESC1608X55N#2 996.02,772.69 r90 top
RT66 "RES_RESC1608X55N_DISCRETE_2K_TM" RESC1608X55N#2 1274.54,772.69 r90 top
RT67 "R_RESC1608X55N_DISCRETE_1.33 K_" RESC1608X55N#2 1334.54,772.69 r90 top
RT68 "RES_RESC1608X55N_DISCRETE_4.99K" RESC1608X55N#2 2285,770.82 r180 top
RT69 "RES_RESC1608X55N_DISCRETE_2.2K_" RESC1608X55N#2 -1225,740 r180 top
RT70 "RES_RESC1608X55N_DISCRETE_2.2K_" RESC1608X55N#2 -965,740 r180 top
RT71 "RES_RESC1608X55N_DISCRETE_2.2K_" RESC1608X55N#2 -705,740 r180 top
RT72 "RES_RESC3216X65N_DISCRETE_27_TM" RESC3216X65N 517.5,732.69 r90 top
RT73 "RES_RESC3216X65N_DISCRETE_27_TM" RESC3216X65N 856.02,732.69 r90 top
RT74 "RES_RESC3216X65N_DISCRETE_27_TM" RESC3216X65N 1194.54,732.69 r90 top
RT75 "RES_RESC1608X55N_DISCRETE_1.8 K" RESC1608X55N#2 2285,711.88 r180 top
RT76 "RES_RESC3216X65N_DISCRETE_249 K" RESC3216X65N 2548.58,711.88 r180 top
RT77 "RES_RESC3216X65N_DISCRETE_249 K" RESC3216X65N 2723.59,711.88 r180 top
RT78 "RES_RESC3216X65N_DISCRETE_249 K" RESC3216X65N 2898.58,711.88 r180 top
RT79 "RES_RESC3216X65N_DISCRETE_249 K" RESC3216X65N 3073.6,711.88 r180 top
RT80 "RES_RESC3216X65N_DISCRETE_249 K" RESC3216X65N 3248.58,711.88 r180 top
RT81 "RES_RESC3216X65N_DISCRETE_249 K" RESC3216X65N 3423.58,711.88 r180 top
RT82 "R_RESC1608X65N_DISCRETE_10K_TMP" RESC1608X65N -355,655 r0 top
RT83 "PTC_RESC2012X60N_DISCRETE_10 KO" RESC2012X60N -220,655 r0 top
RT84 "RES_RESC2012X70N_DISCRETE_0_TMP" RESC2012X70N -1145,565 r90 top
RT85 "RES_RESC2012X70N_DISCRETE_0_TMP" RESC2012X70N -885,565 r90 top
RT86 "RES_RESC2012X70N_DISCRETE_0_TMP" RESC2012X70N -625,565 r90 top
RT87 "RES_RESC1608X55N_DISCRETE_4.99K" RESC1608X55N#2 2285,472.82 r180 top
RT88 "RES_RESC1608X55N_DISCRETE_1.8 K" RESC1608X55N#2 2285,417.82 r180 top
RT89 "R_RESC1608X55N_DISCRETE_15K_TMP" RESC1608X55N#2 -130,384.84 r90 top
RT90 "RES_RESC1608X55N_DISCRETE_4.99K" RESC1608X55N#2 2285,311.76 r180 top
RT91 "RES_RESC1608X55N_DISCRETE_100_T" RESC1608X55N#2 -985.5,299.17 r90 top
RT92 "RES_RESC1608X55N_DISCRETE_100_T" RESC1608X55N#2 -586.5,275.84 r90 top
RT93 "RES_RESC1608X55N_DISCRETE_1.8 K" RESC1608X55N#2 2285,252.82 r180 top
RT94 "RES_RESC3216X65N_DISCRETE_249 K" RESC3216X65N 2548.58,252.82 r180 top
RT95 "RES_RESC3216X65N_DISCRETE_249 K" RESC3216X65N 2723.59,252.82 r180 top
RT96 "RES_RESC3216X65N_DISCRETE_249 K" RESC3216X65N 2898.6,252.82 r180 top
RT97 "RES_RESC3216X65N_DISCRETE_249 K" RESC3216X65N 3073.58,252.82 r180 top
RT98 "RES_RESC3216X65N_DISCRETE_249 K" RESC3216X65N 3248.58,252.82 r180 top
RT99 "RES_RESC3216X65N_DISCRETE_249 K" RESC3216X65N 3423.58,252.82 r180 top
RT100 "R_RESC1608X55N_DISCRETE_15K_TMP" RESC1608X55N#2 -1010,205 r0 top
RT101 "R_RESC1608X55N_DISCRETE_15K_TMP" RESC1608X55N#2 -567,182 r0 top
RT102 "RES_RESC1608X55N_DISCRETE_100_T" RESC1608X55N#2 -983.5,109.17 r270 top
RT103 "RES_RESC1608X55N_DISCRETE_100_T" RESC1608X55N#2 -589.5,85.84 r270 top
RT104 "RES_RESC1608X55N_DISCRETE_100_T" RESC1608X55N#2 -250,-35 r180 top
RT105 "RES_RESC1608X55N_DISCRETE_100_T" RESC1608X55N#2 -69.16,-35 r0 top
RT106 "R_RESC1608X55N_DISCRETE_15K_TMP" RESC1608X55N#2 -160,-61.28 r90 top
RT107 "R_RESC1608X65N_DISCRETE_10K_TMP" RESC1608X65N -503.29,-155.84 r180 top
RT108 "R_RESC1608X55N_DISCRETE_120_TMP" RESC1608X55N#2 -418.28,-180.84 r270 top
RT109 "R_RESC2012X60N_DISCRETE_499_TMP" RESC2012X60N -3045,-330 r180 top
RT110 "R_RESC2012X60N_DISCRETE_249_TMP" RESC2012X60N -2330,-330 r180 top
RT111 "R_RESC1608X55N_DISCRETE_15K_TMP" RESC1608X55N#2 1855,-385 r0 top
RT112 "R_RESC1608X55N_DISCRETE_15K_TMP" RESC1608X55N#2 -290,-545 r0 top
RT113 "R_RESC1608X55N_DISCRETE_120_TMP" RESC1608X55N#2 1640,-560 r0 top
RT114 "R_RESC1608X55N_DISCRETE_15K_TMP" RESC1608X55N#2 240,-565 r180 top
RT115 "R_RESC1608X55N_DISCRETE_120_TMP" RESC1608X55N#2 3700,-644 r0 top
RT116 "R_RESC2013X65N_DISCRETE_1.8K_TM" RESC2013X65N -420,-690 r180 top
RT117 "R_RESC1608X65N_DISCRETE_10K_TMP" RESC1608X65N 3675,-729 r270 top
RT118 "R_RESC1608X55N_DISCRETE_120_TMP" RESC1608X55N#2 1640,-745 r0 top
RT119 "R_RESC2013X65N_DISCRETE_1.8K_TM" RESC2013X65N 525,-775 r0 top
RT120 "R_RESC1608X55N_DISCRETE_15K_TMP" RESC1608X55N#2 1835,-810 r0 top
RT121 "R_RESC1608X55N_DISCRETE_180K_TM" RESC1608X55N#2 3760,-910 r90 top
RT122 "R_RESC1608X65N_DISCRETE_10K_TMP" RESC1608X65N 3695,-955 r90 top
RT123 "R_RESC1608X65N_DISCRETE_10K_TMP" RESC1608X65N 4134,-1026 r90 top
RT124 "R_RESC1608X65N_DISCRETE_10K_TMP" RESC1608X65N 5131,-1030 r180 top
RT125 "R_RESC1608X55N_DISCRETE_100K_TM" RESC1608X55N#2 3670,-1040 r0 top
RT126 "RES_RESC1608X55N_DISCRETE_45.3K" RESC1608X55N#2 4044,-1053 r180 top
RT127 "R_RESC1608X55N_DISCRETE_120_TMP" RESC1608X55N#2 5216.02,-1055 r270 top
RT128 "R_RESC1608X55N_DISCRETE_56K_TMP" RESC1608X55N#2 4219,-1059 r0 top
RT129 "RES_RESC1608X55N_DISCRETE_165K_" RESC1608X55N#2 4590,-1075 r90 top
RT130 "R_RESC1608X65N_DISCRETE_10K_TMP" RESC1608X65N 4515,-1120 r90 top
RT131 "R_RESC1608X65N_DISCRETE_10K_TMP" RESC1608X65N 4964,-1191 r90 top
RT132 "R_RESC1608X55N_DISCRETE_56K_TMP" RESC1608X55N#2 5014,-1191 r90 top
RT133 "R_RESC1608X55N_DISCRETE_100K_TM" RESC1608X55N#2 4480,-1205 r0 top
RT134 "RES_RESC1608X55N_DISCRETE_45.3K" RESC1608X55N#2 4874,-1218 r180 top
RT135 "R_RESC1608X55N_DISCRETE_100K_TM" RESC1608X55N#2 4835,-1520 r270 top
RT136 "R_RESC1608X55N_DISCRETE_100K_TM" RESC1608X55N#2 -4107.5,-1631.67 r270 top
RT137 "R_RESC2012X60N_DISCRETE_2.43K_T" RESC2012X60N 3834.22,-1653.47 r0 top
RT138 "R_RESC2012X60N_DISCRETE_2.43K_T" RESC2012X60N 4638.38,-1653.47 r180 top
RT139 "R_RESC1608X55N_DISCRETE_22K_TMP" RESC1608X55N#2 -4012.5,-1656.67 r0 top
RT140 "R_RESC1608X55N_DISCRETE_200K_TM" RESC1608X55N#2 -4317.5,-1666.67 r0 top
RT141 "RES_RESC6432X70N_DISCRETE_0.01_" RESC6432X70N -3855,-1703.33 r90 top
RT142 "R_RESC1608X55N_DISCRETE_100K_TM" RESC1608X55N#2 -4317.5,-1716.67 r180 top
RT143 "R_RESC1608X55N_DISCRETE_2.7 M_T" RESC1608X55N#2 -4317.5,-1766.67 r0 top
RT144 "R_RESC1608X55N_DISCRETE_2.7 M_T" RESC1608X55N#2 -4317.5,-1816.67 r180 top
UB1 "REF3312AIDCKR - VREF_0_SOT_23_3" SOT_23_3 2164.25,854.17 r180 bottom
UB2 "REF3312AIDCKR - VREF_0_SOT_23_1" SOT_23_3 214.25,834.16 r180 bottom
UB3 "AND3_1X_6PIN_SOT_23_6_IC_SN74LV" SOT_23_6 -1310,100 r90 bottom
UT1 "AD8615_SOT23-5_0_95X2_70P_H1_22" SOT23-5_0_95X2_70P_H1_22 2145,1765 r90 top
UT2 "AD8615_SOT23-5_0_95X2_70P_H1_22" SOT23-5_0_95X2_70P_H1_22 2145,1305.94 r90 top
UT3 "AD8615_SOT23-5_0_95X2_70P_H1_22" SOT23-5_0_95X2_70P_H1_22 -1193.15,1052.4 r0 top
UT4 "AD8615_SOT23-5_0_95X2_70P_H1_22" SOT23-5_0_95X2_70P_H1_22 -933.97,1052.4 r0 top
UT5 "AD8615_SOT23-5_0_95X2_70P_H1_22" SOT23-5_0_95X2_70P_H1_22 -674.79,1052.4 r0 top
UT6 "AD8615_SOT23-5_0_95X2_70P_H1_22" SOT23-5_0_95X2_70P_H1_22 -415.61,1052.4 r0 top
UT7 "AD8615_SOT23-5_0_95X2_70P_H1_22" SOT23-5_0_95X2_70P_H1_22 652.5,1017.69 r0 top
UT8 "AD8615_SOT23-5_0_95X2_70P_H1_22" SOT23-5_0_95X2_70P_H1_22 991.02,1017.69 r0 top
UT9 "AD8615_SOT23-5_0_95X2_70P_H1_22" SOT23-5_0_95X2_70P_H1_22 1329.54,1017.69 r0 top
UT10 "AD8615_SOT23-5_0_95X2_70P_H1_22" SOT23-5_0_95X2_70P_H1_22 -1507.5,915.64 r270 top
UT11 "ISO1050DUB_SMD-8_GULL_WING_V2_I" SMD-8_GULL_WING_V2 -4365,895 r180 top
UT12 "AD8615_SOT23-5_0_95X2_70P_H1_22" SOT23-5_0_95X2_70P_H1_22 2145,846.88 r90 top
UT13 "F28379D-LAUNCHPAD_F28379D-LAUNC" F28379D-LAUNCHPAD-1 525,660 r180 top
UT14 "74LVC123_VFSOP-8_IC_74LVC123_TM" VFSOP-8 -1235,565 r90 top
UT15 "74LVC123_VFSOP-8_IC_74LVC123_TM" VFSOP-8 -975,565 r90 top
UT16 "74LVC123_VFSOP-8_IC_74LVC123_TM" VFSOP-8 -715,565 r90 top
UT17 "R1SE-0505-R_8-SMD-5LEADS_IC_R1S" 8-SMD-5LEADS -4360,415 r270 top
UT18 "AD8615_SOT23-5_0_95X2_70P_H1_22" SOT23-5_0_95X2_70P_H1_22 2145,387.82 r90 top
UT19 "DIFFRCVR_4XG_16P_TSSOP-16P_P65M" TSSOP-16P_P65MM -790,195 r0 top
UT20 "DIFFRCVR_4XG_16P_TSSOP-16P_P65M" TSSOP-16P_P65MM -145,165 r90 top
UT21 "MOSFET_N_GSD_SOT_23_3_DISCRETE_" SOT_23_3 -504.29,-305.84 r0 top
UT22 "74-541_20P_SOP65P640X120-20AN_I" SOP65P640X120-20AN -1440,-560 r270 top
UT23 "74-541_20P_SOP65P640X120-20AN_I" SOP65P640X120-20AN -990,-560 r270 top
UT24 "DIFFDRVR_4X_16P_TSSOP-16P_P65MM" TSSOP-16P_P65MM -55,-560 r0 top
UT25 "DIFFDRVR_4X_16P_TSSOP-16P_P65MM" TSSOP-16P_P65MM 1870,-580 r90 top
UT26 "LM7805_TO-220V_IC_R-78E5.0-1.0_" TO-220V -3170,-645 r90 top
UT27 "LM7805_TO-220V_IC_R-78E3.3-1.0_" TO-220V -2470,-645 r90 top
UT28 "MOSFET_N_GSD_SOT_23_3_DISCRETE_" SOT_23_3 3825,-730 r90 top
UT29 "LT3581_MSOP-16-EP_IC_LT3581_TMP" MSOP-16-EP 3850,-1065 r0 top
UT30 "MOSFET_N_GSD_SOT_23_3_DISCRETE_" SOT_23_3 5130,-1180 r0 top
UT31 "LT3581_MSOP-16-EP_IC_LT3581_TMP" MSOP-16-EP 4680,-1230 r0 top
UT32 "LTC4368_MSOP_10_IC_LTC4368IMS-2" MSOP_10 -4097.5,-1756.67 r0 top

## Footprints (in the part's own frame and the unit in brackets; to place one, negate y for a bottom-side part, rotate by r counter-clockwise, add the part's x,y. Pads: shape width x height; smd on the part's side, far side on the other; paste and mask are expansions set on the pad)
2POS_400MIL_TERMINAL [mil] "2POS_400MIL_TERMINAL"
  rect 120x120 hole 70: 1(200,0)
  round 120 hole 70: 2(-200,0)
  silkscreen extent -300,-125 300,125
8-SMD-5LEADS [mil] "8-SMD-5LEADS"
  rect 80x40 smd: 1(-200,150) 2(-200,50) 4(-200,-150) 5(200,-150) 8(200,150)
  silkscreen extent -165,-250 165,250, body extent -250,-250 250,250, height 150
C_0603#1 [mil] "C_0603"
  rect 35x35 smd: 1(35,0) 2(-35,0)
  silkscreen extent -30,-15 30,15, body extent -62,-28 62,28, height 150
C_0603#2 [mil] "C_0603"
  rect 35x35 smd: 1(-35,0) 2(35,0)
  silkscreen extent -30,-15 30,15
CAPC1608X87N#1 [mil] "CAPC1608X87N"
  rect 37.4x39.37 smd: 1(31.5,0) 2(-31.5,0)
  silkscreen extent 0,-16 0,16, body extent -61,-30 61,30, height 150
CAPC1608X87N#2 [mil] "CAPC1608X87N"
  rect 37.4x39.37 smd: 1(-31.5,0) 2(31.5,0)
  silkscreen extent 0,-16 0,16, body extent -61,-30 61,30, height 150
CAPC1608X90N#1 [mil] "CAPC1608X90N"
  rect 37.4x39.37 smd: 1(31.5,0) 2(-31.5,0)
  silkscreen extent 0,-16 0,16, body extent -61,-30 61,30, height 150
CAPC1608X90N#2 [mil] "CAPC1608X90N"
  rect 37.4x39.37 smd: 1(-31.5,0) 2(31.5,0)
  silkscreen extent 0,-16 0,16, body extent -61,-30 61,30, height 150
CAPC2012X70N [mil] "CAPC2012X70N"
  rect 45.28x57.09 smd: 1(-35.43,0) 2(35.43,0)
  silkscreen extent 0,-26 0,26, body extent -69,-39 69,39, height 150
CAPC2012X135N [mil] "CAPC2012X135N"
  rect 41.34x55.12 smd: 1(-35.43,0) 2(35.43,0)
  silkscreen extent 0,-24 0,24, body extent -67,-37 67,37, height 150
CAPC3216X180N [mil] "CAPC3216X180N"
  rect 45.28x70.87 smd: 1(-59.06,0) 2(59.06,0)
  silkscreen extent -22,-35 22,35, body extent -93,-45 93,45, height 150
CON_1X2_VERT_LOCK [mil] "CON_1X2_VERT_LOCK"
  rect 70x70 hole 45: 1(0,50)
  round 70 hole 45: 2(0,-50)
  silkscreen extent -125,-100 125,100, body extent -130,-105 130,105, height 150
CON_1X3_VERT_LOCK [mil] "CON_1X3_VERT_LOCK"
  rect 70x70 hole 45: 1(0,100)
  round 70 hole 45: 2(0,0) 3(0,-100)
  silkscreen extent -125,-150 125,150, body extent -130,-155 130,155, height 150
CON_2X8_SHROUDED_CORRECTED [mil] "CON_2X8_SHROUDED_CORRECTED"
  rect 70x70 hole 45: 1(-50,350)
  round 70 hole 45: 2(50,350) 3(-50,250) 4(50,250) 5(-50,150) 6(50,150) 7(-50,50) 8(50,50) 9(-50,-50) 10(50,-50) 11(-50,-150) 12(50,-150) 13(-50,-250) 14(50,-250) 15(-50,-350) 16(50,-350)
  silkscreen extent -180,-550 180,550, body extent -180,-550 180,550, height 150
D_0805 [mil] "D_0805"
  rect 35x60 smd: 1(-35,0) 2(35,0)
  silkscreen extent -40,-25 40,25, body extent -63,-40 63,40, height 150
D_1409 [mil] "D_1409"
  rect 60x90 smd: 1(-60,0) 2(60,0)
  silkscreen extent -70,-55 70,55, body extent -100,-55 100,55, height 150
DB9 [mil] "DB9"
  rect 60x60 / inner round 55 / far side rect 60x60 hole 36: 1(216,-378)
  round 60 / inner round 55 / far side round 60 hole 36: 2(108,-378) 3(0,-378) 4(-108,-378) 5(-216,-378) 6(162,-270) 7(54,-270) 8(-54,-270) 9(-162,-270)
  round 250 / inner round 130 / far side round 250 hole 130: 10(486,-324) 11(-486,-324)
  silkscreen extent -652,-474 648,451, body extent -648,-486 648,486, height 150
F28379D-LAUNCHPAD-1 [mil] "F28379D-LAUNCHPAD-1"
  round 70 hole 45: 1(-1305,-900) 2(-1205,-900) 3(-1105,-900) 4(-1005,-900) 5(-905,-900) 6(-805,-900) 7(-705,-900) 8(-605,-900) 9(-505,-900) 10(-405,-900) 11(-405,900) 12(-505,900) 13(-605,900) 14(-705,900) 15(-805,900) 16(-905,900) 17(-1005,900) 18(-1105,900) 19(-1205,900) 20(-1305,900) 21(-1305,-800) 22(-1205,-800) 23(-1105,-800) 24(-1005,-800) 25(-905,-800) 26(-805,-800) 27(-705,-800) 28(-605,-800) 29(-505,-800) 30(-405,-800) 31(-405,800) 32(-505,800) 33(-605,800) 34(-705,800) 35(-805,800) 36(-905,800) 37(-1005,800) 38(-1105,800) 39(-1205,800) 40(-1305,800) 41(1195,-900) 42(1295,-900) 43(1395,-900) 44(1495,-900) 45(1595,-900) 46(1695,-900) 47(1795,-900) 48(1895,-900) 49(1995,-900) 50(2095,-900) 51(2095,900) 52(1995,900) 53(1895,900) 54(1795,900) 55(1695,900) 56(1595,900) 57(1495,900) 58(1395,900) 59(1295,900) 60(1195,900) 61(1195,-800) 62(1295,-800) 63(1395,-800) 64(1495,-800) 65(1595,-800) 66(1695,-800) 67(1795,-800) 68(1895,-800) 69(1995,-800) 70(2095,-800) 71(2095,800) 72(1995,800) 73(1895,800) 74(1795,800) 75(1695,800) 76(1595,800) 77(1495,800) 78(1395,800) 79(1295,800) 80(1195,800) 81(-267.83,-790.79) 82(-267.83,-890.79) 83(-167.83,-790.79) 84(-167.83,-890.79) 85(-67.83,-790.79) 86(-67.83,-890.79) 87(32.17,-790.79) 88(32.17,-890.79) 89(2495,700) 90(2495,600) 91(2495,500) 92(2495,400) 93(2495,300) 94(2495,100) 95(2495,0) 96(2495,-100) 97(2495,-200) 98(2495,-300) 99(2495,-500) 100(2495,-600) 101(2495,-700) 102(2495,900) 103(2395,900) 104(2295,900) 105(2495,-900) 106(2395,-900) 107(2295,-900)
  body extent -2555,-1150 2555,1150, height 150
IND-5040 [mm] "IND-5040"
  rect 1.5x4 smd: 1(-1.8,0) 2(1.8,0)
  silkscreen extent -2.45,-2.45 2.45,2.45
IND-MSD7342 [mm] "IND-MSD7342"
  rect 2.35x1.1 smd: 1(-2.825,0.85) 2(-2.825,-0.85) 3(2.825,-0.85) 4(2.825,0.85)
  silkscreen extent -3.75,-3.75 3.75,3.75, body extent -3.75,-3.75 3.75,3.75, height 3.81
L_0805 [mil] "L_0805"
  rect 35x60 smd: 1(-35,0) 2(35,0)
  silkscreen extent -40,-25 40,25
MDR-26 [mil] "MDR-26"
  round 40 / inner round 28 / far side round 40 hole 28: 1(300,120) 2(300,270) 3(250,45) 4(250,195) 5(200,120) 6(200,270) 7(150,45) 8(150,195) 9(100,120) 10(100,270) 11(50,45) 12(50,195) 13(0,120) 14(0,270) 15(-50,45) 16(-50,195) 17(-100,120) 18(-100,270) 19(-150,45) 20(-150,195) 21(-200,120) 22(-200,270) 23(-250,45) 24(-250,195) 25(-300,120) 26(-300,270)
  round 150 / inner round 120 / far side round 150 hole 110: ""(-615.5,195) ""(615.5,195)
  silkscreen extent -776,-355 776,355, body extent -776,-355 776,355, height 150
MSOP-16-EP [mil] "MSOP-16-EP"
  rect 35.43x11.81 smd: 1(-88,68.95) 2(-88,49.25) 3(-88,29.55) 4(-88,9.85) 5(-88,-9.85) 6(-88,-29.55) 7(-88,-49.25) 8(-88,-68.95) 9(88,-68.95) 10(88,-49.25) 11(88,-29.55) 12(88,-9.85) 13(88,9.85) 14(88,29.55) 15(88,49.25) 16(88,68.95)
  rect 65x120 smd: 17(0,0)
  silkscreen extent -61,-82 61,82
MSOP_10 [mil] "MSOP_10"
  rect 40x12 smd: 1(-85,40) 2(-85,20) 3(-85,0) 4(-85,-20) 5(-85,-40) 6(85,-40) 7(85,-20) 8(85,0) 9(85,20) 10(85,40)
  silkscreen extent -60,-60 60,60
PHOENIX_SPT5_6PIN [mil] "PHOENIX_SPT5_6PIN"
  round 105 hole 85: 1(-661.42,400.59) 2(-366.14,-119.1) 3(-70.87,400.59) 4(224.41,-119.1) 5(519.68,400.59) 6(814.96,-119.1)
  body extent -921,-475 921,475, height 150
POWER-SO8 [mm] "POWER-SO8"
  rect 0.63x0.65 smd: 1(-2.735,1.905) 2(-2.735,0.635) 3(-2.735,-0.635) 4(-2.735,-1.905) 5(2.735,-1.905) 6(2.735,-0.635) 7(2.735,0.635) 8(2.735,1.905)
  TOP region: 2.745,-2.23 -1.545,-2.23 -1.545,0 2.745,0
  TOP region: 2.745,2.23 -1.545,2.23 -1.545,0 2.745,0
  silkscreen extent -4.17,-2.63 3.03,2.63, body extent -3.61,-2.75 3.61,2.75, height 3.81
POWERJACK-PJ102AH [mil] "POWERJACK-PJ102AH"
  round 90 hole 50: 1(-30,247.5) 2(-30,11.5) 3(155,129.5)
  silkscreen extent -200,-293 200,293, body extent -200,-293 200,293, height 150
RESC1608X55N#1 [mil] "RESC1608X55N"
  rect 35.43x39.37 smd: 1(31.5,0) 2(-31.5,0)
  silkscreen extent 0,-16 0,16, body extent -59,-30 59,30, height 150
RESC1608X55N#2 [mil] "RESC1608X55N"
  rect 35.43x39.37 smd: 1(-31.5,0) 2(31.5,0)
  silkscreen extent 0,-16 0,16, body extent -59,-30 59,30, height 150
RESC1608X65N [mil] "RESC1608X65N"
  rect 35.43x39.37 smd: 1(-31.5,0) 2(31.5,0)
  silkscreen extent 0,-16 0,16, body extent -59,-30 59,30, height 150
RESC2012X60N [mm] "RESC2012X60N"
  rect 0.95x1.4 smd: 1(-1,0) 2(1,0)
  silkscreen extent -0.15,-0.7 0.15,0.7, body extent -1.75,-0.95 1.75,0.95, height 3.81
RESC2012X70N [mil] "RESC2012X70N"
  rect 41.34x55.12 smd: 1(-37.4,0) 2(37.4,0)
  silkscreen extent -2,-28 2,28, body extent -69,-37 69,37, height 150
RESC2013X65N [mm] "RESC2013X65N"
  rect 1x1.45 smd: 1(-0.95,0) 2(0.95,0)
  silkscreen extent -0.05,-0.7 0.05,0.7, body extent -1.7,-1 1.7,1, height 3.81
RESC3216X65N [mil] "RESC3216X65N"
  rect 45.28x70.87 smd: 1(-57.09,0) 2(57.09,0)
  silkscreen extent -20,-35 20,35, body extent -91,-45 91,45, height 150
RESC6432X70N [mil] "RESC6432X70N"
  rect 49.21x133.86 smd: 1(-120.08,0) 2(120.08,0)
  silkscreen extent -81,-67 81,67, body extent -156,-77 156,77, height 150
SMD-8_GULL_WING_V2 [mil] "SMD-8_GULL_WING_V2"
  rect 120x32 smd: 1(-187.5,150) 2(-187.5,50) 3(-187.5,-50) 4(-187.5,-150) 5(187.5,-150) 6(187.5,-50) 7(187.5,50) 8(187.5,150)
  silkscreen extent -133,-190 133,190, body extent -258,-195 258,195, height 150
SOD-123F-AC [mil] "SOD-123F-AC"
  round 1 smd: 1(65,0) 2(-65,0)
  TOP region: -83,25 -83,-25 -47,-25 -47,25
  TOP region: 47,25 47,-25 83,-25 83,25
  silkscreen extent -95,-40 95,40, body extent -95,-40 95,40, height 150
SOD-323-AC [mil] "SOD-323-AC"
  rect 25x33 smd: A(-44,0) C(50,0)
  body extent -70,-30 70,30, height 150
SOP65P640X120-20AN [mil] "SOP65P640X120-20AN"
  rect 59.06x17.72 smd: 1(-116.14,115.16) 2(-116.14,89.57) 3(-116.14,63.98) 4(-116.14,38.39) 5(-116.14,12.8) 6(-116.14,-12.8) 7(-116.14,-38.39) 8(-116.14,-63.98) 9(-116.14,-89.57) 10(-116.14,-115.16) 11(116.14,-115.16) 12(116.14,-89.57) 13(116.14,-63.98) 14(116.14,-38.39) 15(116.14,-12.8) 16(116.14,12.8) 17(116.14,38.39) 18(116.14,63.98) 19(116.14,89.57) 20(116.14,115.16)
  silkscreen extent -141,-130 73,151, body extent -156,-140 156,140, height 150
SOT23-5_0_95X2_70P_H1_22 [mm] "SOT23-5_0_95X2_70P_H1_22"
  rect 1.05x0.6 smd: 1(-1.35,0.95) 2(-1.35,0) 3(-1.35,-0.95) 4(1.35,-0.95) 5(1.35,0.95)
  silkscreen extent -1.77,-1.55 0.45,1.92, body extent -2.15,-1.8 2.15,1.8, height 3.81
SOT_23_3 [mil] "SOT_23_3"
  rect 31x35 smd: 1(37,38) 2(-37,38) 3(0,-41)
  body extent -84,-74 84,74, height 150
SOT_23_6 [mil] "SOT_23_6"
  rect 24x42 smd: 1(37.5,52.5) 2(0,52.5) 3(-37.5,52.5) 4(-37.5,-53.5) 5(0,-53.5) 6(37.5,-53.5)
  silkscreen extent -62,-18 62,18, body extent -63,-88 63,88, height 150
TO-220V [mm] "TO-220V"
  rect 2x2 / inner round 2 / far side rect 2x2 hole 1.2: 1(-2.54,-0.75)
  round 2 hole 1.2: 2(0,-0.75) 3(2.54,-0.75)
  silkscreen extent -5.3,-3.13 5.3,2.45, body extent -5.55,-2.7 5.55,2.7, height 3.81
TSSOP-16P_P65MM [mil] "TSSOP-16P_P65MM"
  oval 62.99x17.72 smd: 1(-112.2,89.57) 2(-112.2,63.98) 3(-112.2,38.39) 4(-112.2,12.8) 5(-112.2,-12.8) 6(-112.2,-38.39) 7(-112.2,-63.98) 8(-112.2,-89.57) 9(112.2,-89.57) 10(112.2,-63.98) 11(112.2,-38.39) 12(112.2,-12.8) 13(112.2,12.8) 14(112.2,38.39) 15(112.2,63.98) 16(112.2,89.57)
  silkscreen extent -139,-98 68,123, body extent -154,-110 154,110, height 150
VFSOP-8 [mil] "VFSOP-8"
  rect 30x10 smd: 1(-61,30) 2(-61,10) 3(-61,-10) 4(-61,-30) 5(61,-30) 6(61,-10) 7(61,10) 8(61,30)
  silkscreen extent -112,-45 30,59, body extent -80,-45 80,45, height 150

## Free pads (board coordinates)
  round 60 smd: ""(-4531.14,-1473.35) ""(-4531.14,1752.13) ""(-1102.4,-1228.47) ""(0,1752.13) ""(1102.32,-1228.47) ""(5078.74,-1936.89) ""(5078.74,1228.35)

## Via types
v1: diameter 24, hole 13, TOP to BOTTOM, 503 vias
